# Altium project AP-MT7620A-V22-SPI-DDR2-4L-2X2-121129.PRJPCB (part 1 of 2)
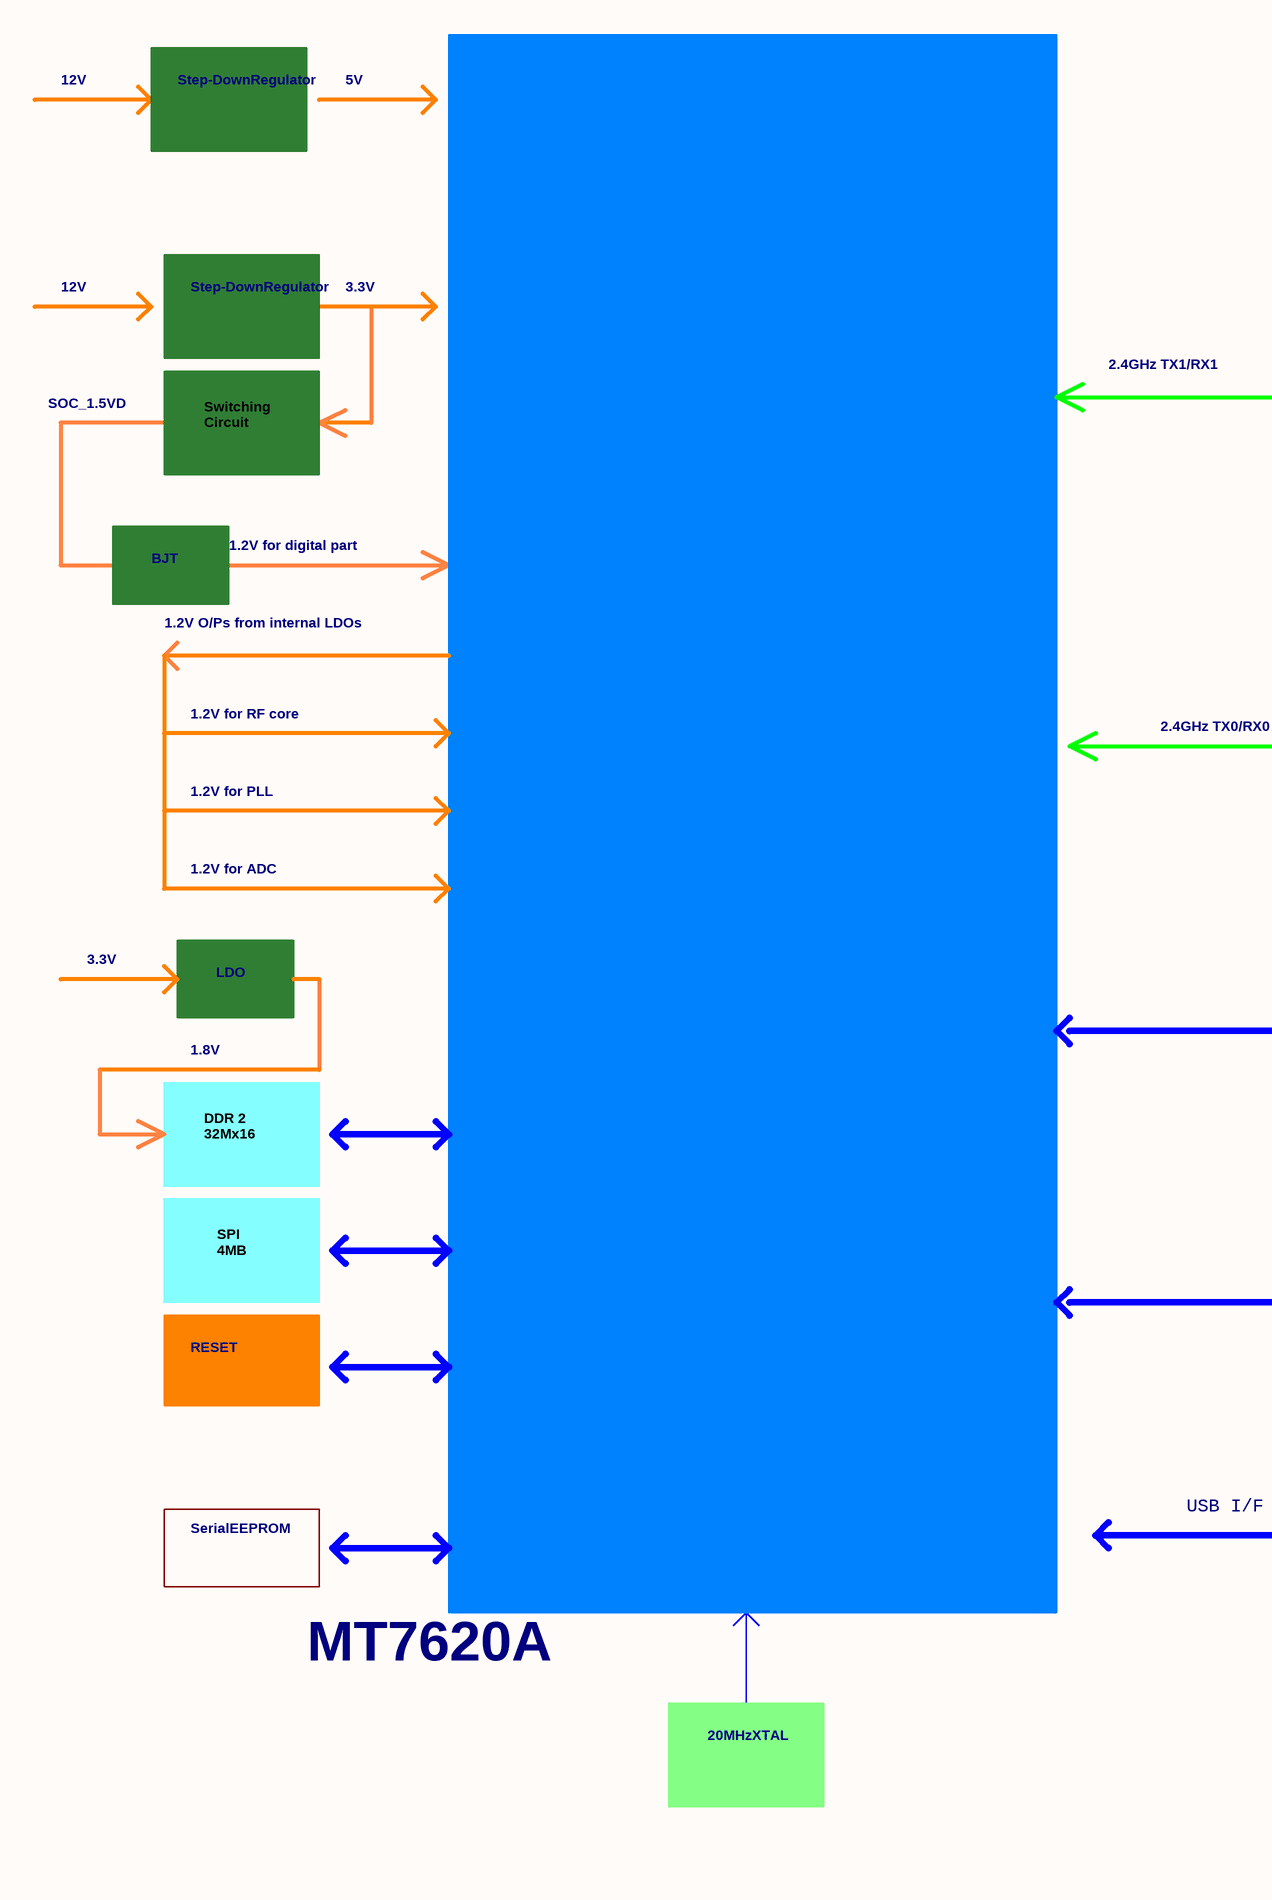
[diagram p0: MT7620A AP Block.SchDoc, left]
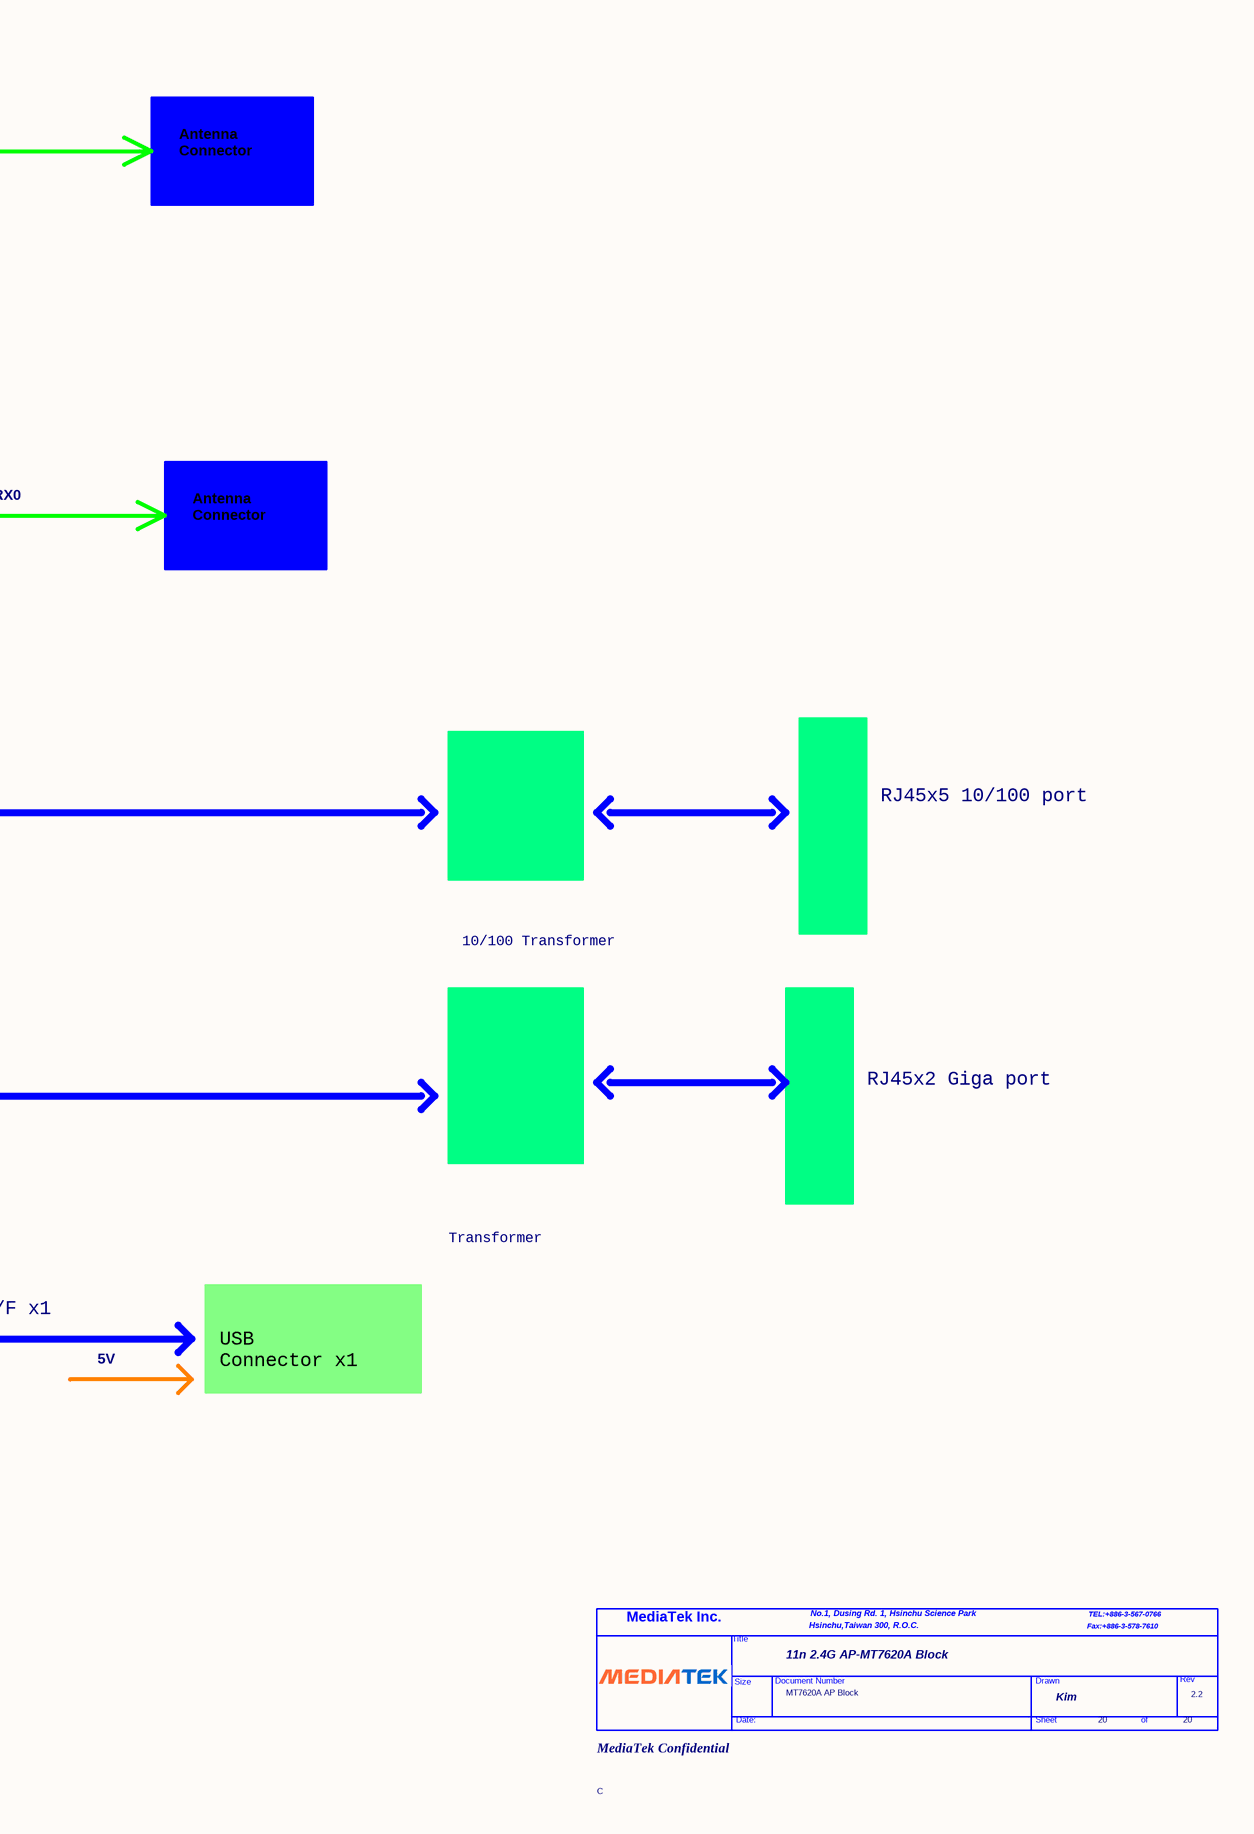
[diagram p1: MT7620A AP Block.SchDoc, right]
20 sheets, 652 parts. Net scope: hierarchical (ports join the sheet entries above them; power ports are global).
Board file: AP-MT7620A-V22-SPI-DDR2-4L-2X2-121129-WS2120.PCBDOC
Sheets:
  MT7620A AP Block.SchDoc
  AP-MT7620A-V22.SchDoc
    2-MEMORY = 23-CONFIG.SchDoc
    2-MEMORY = 22-DDR-CFG.SchDoc
    2-MEMORY = 21-SPI Flash.SchDoc
    3-WLAN = 32-RT5592EP-solt-5G.SchDoc
    3-WLAN = 31-Antenna.SchDoc
    4-ETHERNET = 43-GE2-XMER-RJ45.SchDoc
    4-ETHERNET = 42-GE-XMER-RJ45.SchDoc
    4-ETHERNET = 41-XMER-RJ45.SchDoc
    5-POWER = 5-POWER-RESET.SchDoc
    1-CPU-MT7620A = 18-GPHY2-IP1001.SchDoc
    1-CPU-MT7620A = 17-GPHY1-IP1001.SchDoc
    1-CPU-MT7620A = 16-MT7620A Power-F.SchDoc
    1-CPU-MT7620A = 15-MT7620A Ethernet-E.SchDoc
    1-CPU-MT7620A = 14-MT7620A USB and PCIE.SchDoc
    1-CPU-MT7620A = 13-MT7620A Peripheral-C.SchDoc
    1-CPU-MT7620A = 12-MT7620A DDR I_F-B.SchDoc
    1-CPU-MT7620A = 11-MT7620A RF Front End.SchDoc
    6-LED = 6-LED.SchDoc

## Sheet MT7620A AP Block.SchDoc
size 513 x 386 mm

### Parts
(Parts that share a designator on the sheet are numbered #1, #2 ... from top to bottom, then left to right.)
*#1  PIM: MediaTek Confidential  Page Count: 20  Page Size: C  Title: 11n 2.4G AP-MT7620A Block  RevCode: 2.2  Doc: MT7620A AP Block  Designer: Kim  (hidden comment: TitleBlock_MTK4)  (graphical)

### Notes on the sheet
- 12V
- Step-DownRegulator
- 5V
- 3.3V
- 2.4GHz TX1/RX1
- SOC_1.5VD
- Switching
  Circuit
- Antenna
  Connector
- BJT
- 1.2V for digital part
- 1.2V O/Ps from internal LDOs
- 1.2V for RF core
- 2.4GHz TX0/RX0
- 1.2V for PLL
- 1.2V for ADC
- LDO
- RJ45x5 10/100 port
- 1.8V
- DDR 2
  32Mx16
- 10/100 Transformer
- SPI
  4MB
- RJ45x2 Giga port
- RESET
- Transformer
- SerialEEPROM
- USB I/F x1
- USB
  Connector x1
- MT7620A
- 20MHzXTAL

## Sheet AP-MT7620A-V22.SchDoc
size 386 x 246 mm
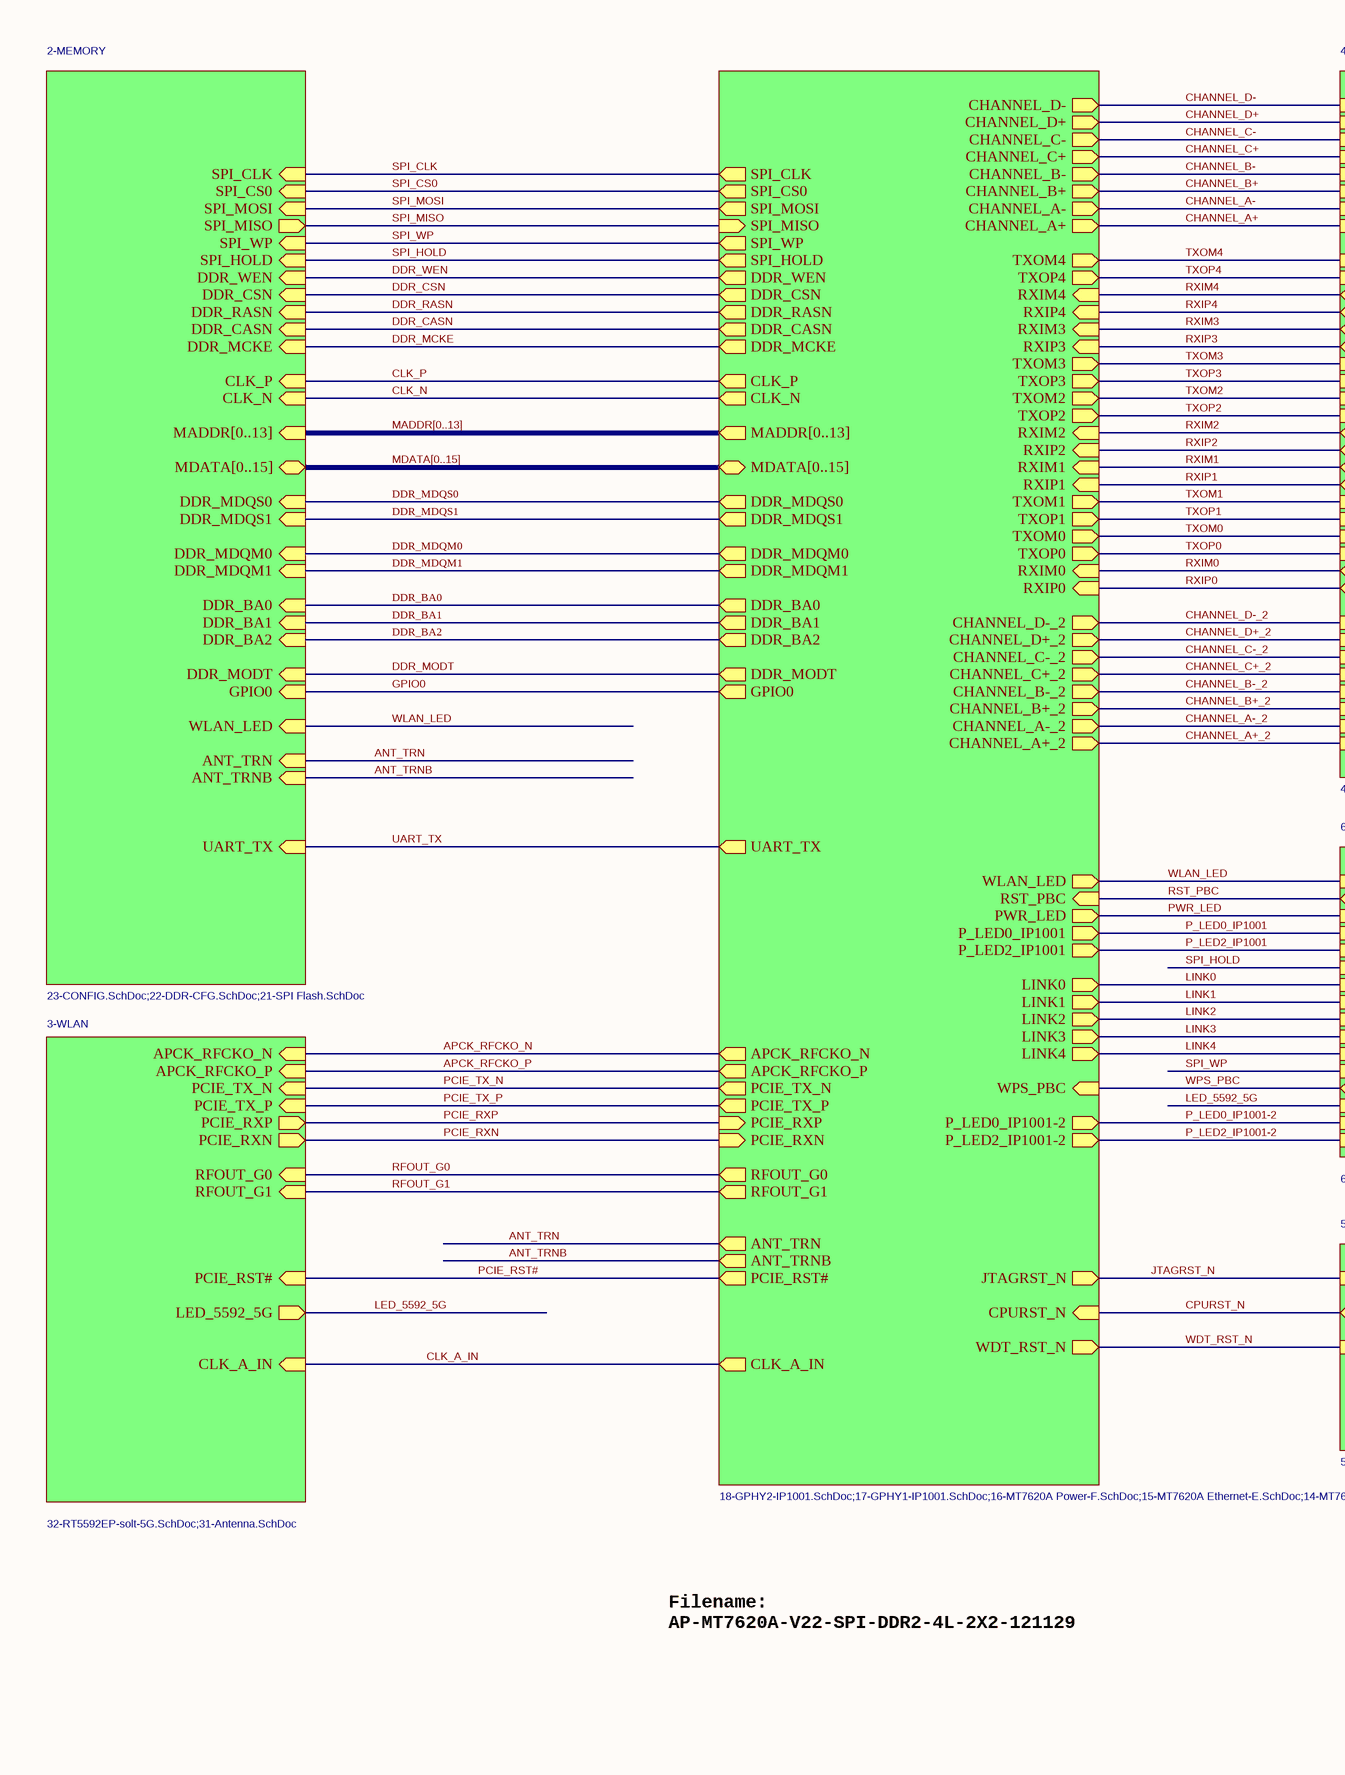
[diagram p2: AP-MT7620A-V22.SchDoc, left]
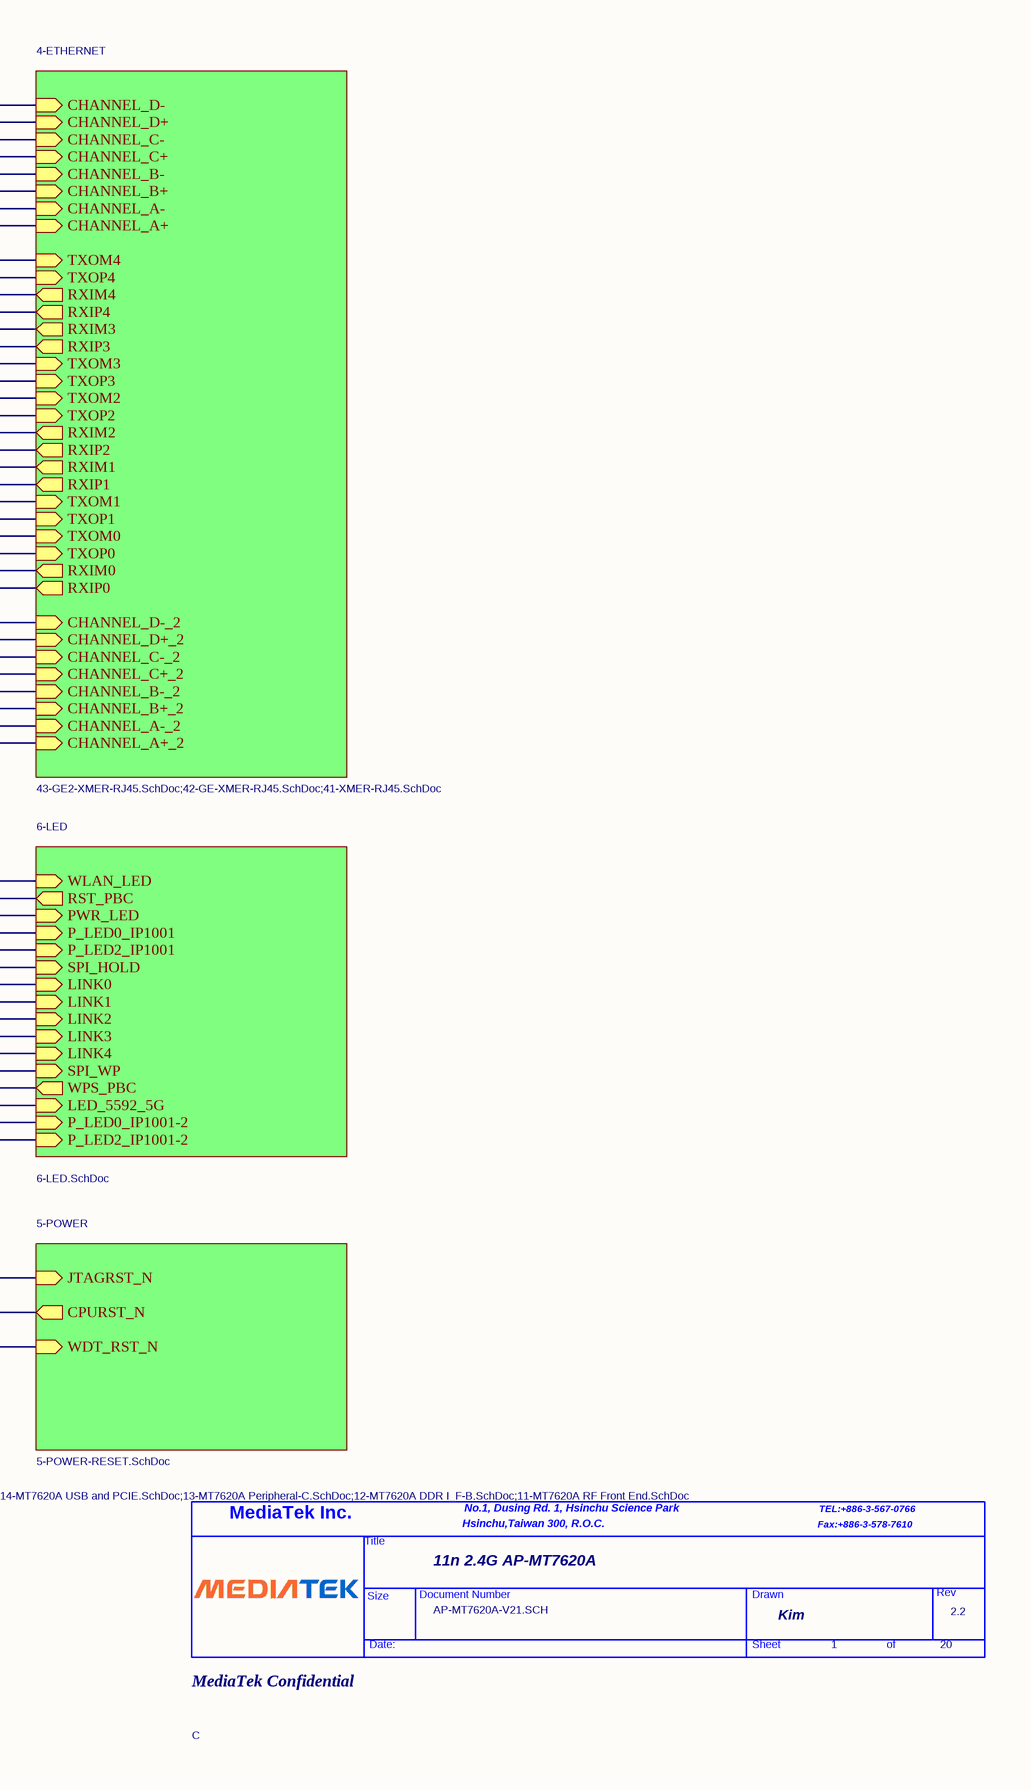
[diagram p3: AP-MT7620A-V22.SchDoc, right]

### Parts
(Parts that share a designator on the sheet are numbered #1, #2 ... from top to bottom, then left to right.)
*#2  PIM: MediaTek Confidential  Page Count: 20  Page Number: 1  Page Size: C  Title: 11n 2.4G AP-MT7620A  RevCode: 2.2  Doc: AP-MT7620A-V21.SCH  Designer: Kim  (hidden comment: TitleBlock_MTK4)  (graphical)

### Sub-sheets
1-CPU-MT7620A = 18-GPHY2-IP1001.SchDoc;17-GPHY1-IP1001.SchDoc;16-MT7620A Power-F.SchDoc;15-MT7620A Ethernet-E.SchDoc;14-MT7620A USB and PCIE.SchDoc;13-MT7620A Peripheral-C.SchDoc;12-MT7620A DDR I_F-B.SchDoc;11-MT7620A RF Front End.SchDoc: SPI_CLK (out), DDR_WEN (out), DDR_CSN (out), CLK_P (out), SPI_CS0 (out), DDR_RASN (out), MADDR[0..13] (out), MDATA[0..15] (bidir), TXOM4 (out), TXOP4 (out), RXIM4 (in), RXIP4 (in), ANT_TRN (out), ANT_TRNB (out), CPURST_N (in), RFOUT_G0 (out), RFOUT_G1 (out), LINK3 (out), LINK2 (out), LINK0 (out), LINK1 (out), LINK4 (out), RXIM3 (in), RXIP0 (in), RXIP1 (in), RXIP2 (in), RXIP3 (in), RXIM0 (in), RXIM1 (in), RXIM2 (in), TXOP0 (out), TXOP1 (out), TXOP2 (out), TXOP3 (out), TXOM0 (out), TXOM1 (out), TXOM2 (out), TXOM3 (out), WPS_PBC (in), DDR_MDQS0 (out), DDR_MDQM0 (out), CLK_N (out), DDR_CASN (out), DDR_BA0 (out), DDR_MCKE (out), SPI_MOSI (out), SPI_MISO (in), UART_TX (out), WLAN_LED (out), SPI_WP (out), SPI_HOLD (out), WDT_RST_N (out), PCIE_RXN (in), PCIE_RXP (in), PCIE_TX_P (out), PCIE_TX_N (out), APCK_RFCKO_P (out), APCK_RFCKO_N (out), CHANNEL_A+ (out), CHANNEL_A- (out), CHANNEL_B+ (out), CHANNEL_B- (out), CHANNEL_C+ (out), CHANNEL_C- (out), CHANNEL_D+ (out), CHANNEL_D- (out), P_LED0_IP1001 (out), P_LED2_IP1001 (out), PCIE_RST# (out), RST_PBC (in), PWR_LED (out), JTAGRST_N (out), DDR_MODT (out), CHANNEL_D-_2 (out), CHANNEL_D+_2 (out), CHANNEL_C-_2 (out), CHANNEL_C+_2 (out), CHANNEL_B-_2 (out), CHANNEL_B+_2 (out), CHANNEL_A-_2 (out), CHANNEL_A+_2 (out), P_LED0_IP1001-2 (out), P_LED2_IP1001-2 (out), GPIO0 (out), CLK_A_IN (out), DDR_MDQS1 (out), DDR_MDQM1 (out), DDR_BA1 (out), DDR_BA2 (out)
2-MEMORY = 23-CONFIG.SchDoc;22-DDR-CFG.SchDoc;21-SPI Flash.SchDoc: SPI_CLK (in), DDR_CSN (in), DDR_WEN (in), CLK_P (in), SPI_CS0 (in), DDR_RASN (in), MADDR[0..13] (in), MDATA[0..15] (bidir), DDR_MDQS0 (in), DDR_MDQM0 (in), CLK_N (in), DDR_CASN (in), DDR_BA0 (in), DDR_MCKE (in), SPI_MOSI (in), SPI_MISO (out), ANT_TRNB (in), ANT_TRN (in), UART_TX (in), GPIO0 (in), SPI_WP (in), SPI_HOLD (in), WLAN_LED (in), DDR_MODT (in), DDR_MDQS1 (in), DDR_MDQM1 (in), DDR_BA1 (in), DDR_BA2 (in)
3-WLAN = 32-RT5592EP-solt-5G.SchDoc;31-Antenna.SchDoc: RFOUT_G0 (in), RFOUT_G1 (in), APCK_RFCKO_N (in), APCK_RFCKO_P (in), PCIE_TX_N (in), PCIE_TX_P (in), PCIE_RXP (out), PCIE_RXN (out), LED_5592_5G (out), PCIE_RST# (in), CLK_A_IN (in)
4-ETHERNET = 43-GE2-XMER-RJ45.SchDoc;42-GE-XMER-RJ45.SchDoc;41-XMER-RJ45.SchDoc: TXOM4 (in), TXOP4 (in), RXIM4 (out), RXIP4 (out), RXIM3 (out), RXIP3 (out), TXOM3 (in), TXOP3 (in), TXOM2 (in), TXOP2 (in), RXIM2 (out), RXIP2 (out), RXIM1 (out), RXIP1 (out), TXOM1 (in), TXOP1 (in), TXOM0 (in), TXOP0 (in), RXIM0 (out), RXIP0 (out), CHANNEL_A+ (in), CHANNEL_A- (in), CHANNEL_B+ (in), CHANNEL_B- (in), CHANNEL_C+ (in), CHANNEL_C- (in), CHANNEL_D+ (in), CHANNEL_D- (in), CHANNEL_D-_2 (in), CHANNEL_D+_2 (in), CHANNEL_C-_2 (in), CHANNEL_C+_2 (in), CHANNEL_B-_2 (in), CHANNEL_B+_2 (in), CHANNEL_A-_2 (in), CHANNEL_A+_2 (in)
5-POWER = 5-POWER-RESET.SchDoc: CPURST_N (out), WDT_RST_N (in), JTAGRST_N (in)
6-LED = 6-LED.SchDoc: LINK0 (in), LINK1 (in), LINK2 (in), LINK3 (in), LINK4 (in), WPS_PBC (out), WLAN_LED (in), P_LED0_IP1001 (in), P_LED2_IP1001 (in), LED_5592_5G (in), RST_PBC (out), PWR_LED (in), SPI_HOLD (in), SPI_WP (in), P_LED2_IP1001-2 (in), P_LED0_IP1001-2 (in)

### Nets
ANT_TRN: sheet 2-MEMORY/ANT_TRN, sheet 1-CPU-MT7620A/ANT_TRN
ANT_TRNB: sheet 2-MEMORY/ANT_TRNB, sheet 1-CPU-MT7620A/ANT_TRNB
APCK_RFCKO_N: sheet 3-WLAN/APCK_RFCKO_N, sheet 1-CPU-MT7620A/APCK_RFCKO_N
APCK_RFCKO_P: sheet 3-WLAN/APCK_RFCKO_P, sheet 1-CPU-MT7620A/APCK_RFCKO_P
CHANNEL_A+: sheet 4-ETHERNET/CHANNEL_A+, sheet 1-CPU-MT7620A/CHANNEL_A+
CHANNEL_A+_2: sheet 4-ETHERNET/CHANNEL_A+_2, sheet 1-CPU-MT7620A/CHANNEL_A+_2
CHANNEL_A-: sheet 4-ETHERNET/CHANNEL_A-, sheet 1-CPU-MT7620A/CHANNEL_A-
CHANNEL_A-_2: sheet 4-ETHERNET/CHANNEL_A-_2, sheet 1-CPU-MT7620A/CHANNEL_A-_2
CHANNEL_B+: sheet 4-ETHERNET/CHANNEL_B+, sheet 1-CPU-MT7620A/CHANNEL_B+
CHANNEL_B+_2: sheet 4-ETHERNET/CHANNEL_B+_2, sheet 1-CPU-MT7620A/CHANNEL_B+_2
CHANNEL_B-: sheet 4-ETHERNET/CHANNEL_B-, sheet 1-CPU-MT7620A/CHANNEL_B-
CHANNEL_B-_2: sheet 4-ETHERNET/CHANNEL_B-_2, sheet 1-CPU-MT7620A/CHANNEL_B-_2
CHANNEL_C+: sheet 4-ETHERNET/CHANNEL_C+, sheet 1-CPU-MT7620A/CHANNEL_C+
CHANNEL_C+_2: sheet 4-ETHERNET/CHANNEL_C+_2, sheet 1-CPU-MT7620A/CHANNEL_C+_2
CHANNEL_C-: sheet 4-ETHERNET/CHANNEL_C-, sheet 1-CPU-MT7620A/CHANNEL_C-
CHANNEL_C-_2: sheet 4-ETHERNET/CHANNEL_C-_2, sheet 1-CPU-MT7620A/CHANNEL_C-_2
CHANNEL_D+: sheet 4-ETHERNET/CHANNEL_D+, sheet 1-CPU-MT7620A/CHANNEL_D+
CHANNEL_D+_2: sheet 4-ETHERNET/CHANNEL_D+_2, sheet 1-CPU-MT7620A/CHANNEL_D+_2
CHANNEL_D-: sheet 4-ETHERNET/CHANNEL_D-, sheet 1-CPU-MT7620A/CHANNEL_D-
CHANNEL_D-_2: sheet 4-ETHERNET/CHANNEL_D-_2, sheet 1-CPU-MT7620A/CHANNEL_D-_2
CLK_A_IN: sheet 3-WLAN/CLK_A_IN, sheet 1-CPU-MT7620A/CLK_A_IN
CLK_N: sheet 2-MEMORY/CLK_N, sheet 1-CPU-MT7620A/CLK_N
CLK_P: sheet 2-MEMORY/CLK_P, sheet 1-CPU-MT7620A/CLK_P
CPURST_N: sheet 5-POWER/CPURST_N, sheet 1-CPU-MT7620A/CPURST_N
DDR_BA0: sheet 2-MEMORY/DDR_BA0, sheet 1-CPU-MT7620A/DDR_BA0
DDR_BA1: sheet 2-MEMORY/DDR_BA1, sheet 1-CPU-MT7620A/DDR_BA1
DDR_BA2: sheet 2-MEMORY/DDR_BA2, sheet 1-CPU-MT7620A/DDR_BA2
DDR_CASN: sheet 2-MEMORY/DDR_CASN, sheet 1-CPU-MT7620A/DDR_CASN
DDR_CSN: sheet 2-MEMORY/DDR_CSN, sheet 1-CPU-MT7620A/DDR_CSN
DDR_MCKE: sheet 2-MEMORY/DDR_MCKE, sheet 1-CPU-MT7620A/DDR_MCKE
DDR_MDQM0: sheet 2-MEMORY/DDR_MDQM0, sheet 1-CPU-MT7620A/DDR_MDQM0
DDR_MDQM1: sheet 2-MEMORY/DDR_MDQM1, sheet 1-CPU-MT7620A/DDR_MDQM1
DDR_MDQS0: sheet 2-MEMORY/DDR_MDQS0, sheet 1-CPU-MT7620A/DDR_MDQS0
DDR_MDQS1: sheet 2-MEMORY/DDR_MDQS1, sheet 1-CPU-MT7620A/DDR_MDQS1
DDR_MODT: sheet 2-MEMORY/DDR_MODT, sheet 1-CPU-MT7620A/DDR_MODT
DDR_RASN: sheet 2-MEMORY/DDR_RASN, sheet 1-CPU-MT7620A/DDR_RASN
DDR_WEN: sheet 2-MEMORY/DDR_WEN, sheet 1-CPU-MT7620A/DDR_WEN
GPIO0: sheet 2-MEMORY/GPIO0, sheet 1-CPU-MT7620A/GPIO0
JTAGRST_N: sheet 5-POWER/JTAGRST_N, sheet 1-CPU-MT7620A/JTAGRST_N
LED_5592_5G: sheet 3-WLAN/LED_5592_5G, sheet 6-LED/LED_5592_5G
LINK0: sheet 1-CPU-MT7620A/LINK0, sheet 6-LED/LINK0
LINK1: sheet 1-CPU-MT7620A/LINK1, sheet 6-LED/LINK1
LINK2: sheet 1-CPU-MT7620A/LINK2, sheet 6-LED/LINK2
LINK3: sheet 1-CPU-MT7620A/LINK3, sheet 6-LED/LINK3
LINK4: sheet 1-CPU-MT7620A/LINK4, sheet 6-LED/LINK4
P_LED0_IP1001: sheet 1-CPU-MT7620A/P_LED0_IP1001, sheet 6-LED/P_LED0_IP1001
P_LED0_IP1001-2: sheet 1-CPU-MT7620A/P_LED0_IP1001-2, sheet 6-LED/P_LED0_IP1001-2
P_LED2_IP1001: sheet 1-CPU-MT7620A/P_LED2_IP1001, sheet 6-LED/P_LED2_IP1001
P_LED2_IP1001-2: sheet 1-CPU-MT7620A/P_LED2_IP1001-2, sheet 6-LED/P_LED2_IP1001-2
PCIE_RST#: sheet 3-WLAN/PCIE_RST#, sheet 1-CPU-MT7620A/PCIE_RST#
PCIE_RXN: sheet 3-WLAN/PCIE_RXN, sheet 1-CPU-MT7620A/PCIE_RXN
PCIE_RXP: sheet 3-WLAN/PCIE_RXP, sheet 1-CPU-MT7620A/PCIE_RXP
PCIE_TX_N: sheet 3-WLAN/PCIE_TX_N, sheet 1-CPU-MT7620A/PCIE_TX_N
PCIE_TX_P: sheet 3-WLAN/PCIE_TX_P, sheet 1-CPU-MT7620A/PCIE_TX_P
PWR_LED: sheet 1-CPU-MT7620A/PWR_LED, sheet 6-LED/PWR_LED
RFOUT_G0: sheet 3-WLAN/RFOUT_G0, sheet 1-CPU-MT7620A/RFOUT_G0
RFOUT_G1: sheet 3-WLAN/RFOUT_G1, sheet 1-CPU-MT7620A/RFOUT_G1
RST_PBC: sheet 1-CPU-MT7620A/RST_PBC, sheet 6-LED/RST_PBC
RXIM0: sheet 4-ETHERNET/RXIM0, sheet 1-CPU-MT7620A/RXIM0
RXIM1: sheet 4-ETHERNET/RXIM1, sheet 1-CPU-MT7620A/RXIM1
RXIM2: sheet 4-ETHERNET/RXIM2, sheet 1-CPU-MT7620A/RXIM2
RXIM3: sheet 4-ETHERNET/RXIM3, sheet 1-CPU-MT7620A/RXIM3
RXIM4: sheet 4-ETHERNET/RXIM4, sheet 1-CPU-MT7620A/RXIM4
RXIP0: sheet 4-ETHERNET/RXIP0, sheet 1-CPU-MT7620A/RXIP0
RXIP1: sheet 4-ETHERNET/RXIP1, sheet 1-CPU-MT7620A/RXIP1
RXIP2: sheet 4-ETHERNET/RXIP2, sheet 1-CPU-MT7620A/RXIP2
RXIP3: sheet 4-ETHERNET/RXIP3, sheet 1-CPU-MT7620A/RXIP3
RXIP4: sheet 4-ETHERNET/RXIP4, sheet 1-CPU-MT7620A/RXIP4
SPI_CLK: sheet 2-MEMORY/SPI_CLK, sheet 1-CPU-MT7620A/SPI_CLK
SPI_CS0: sheet 2-MEMORY/SPI_CS0, sheet 1-CPU-MT7620A/SPI_CS0
SPI_HOLD: sheet 2-MEMORY/SPI_HOLD, sheet 1-CPU-MT7620A/SPI_HOLD, sheet 6-LED/SPI_HOLD
SPI_MISO: sheet 2-MEMORY/SPI_MISO, sheet 1-CPU-MT7620A/SPI_MISO
SPI_MOSI: sheet 2-MEMORY/SPI_MOSI, sheet 1-CPU-MT7620A/SPI_MOSI
SPI_WP: sheet 2-MEMORY/SPI_WP, sheet 1-CPU-MT7620A/SPI_WP, sheet 6-LED/SPI_WP
TXOM0: sheet 4-ETHERNET/TXOM0, sheet 1-CPU-MT7620A/TXOM0
TXOM1: sheet 4-ETHERNET/TXOM1, sheet 1-CPU-MT7620A/TXOM1
TXOM2: sheet 4-ETHERNET/TXOM2, sheet 1-CPU-MT7620A/TXOM2
TXOM3: sheet 4-ETHERNET/TXOM3, sheet 1-CPU-MT7620A/TXOM3
TXOM4: sheet 4-ETHERNET/TXOM4, sheet 1-CPU-MT7620A/TXOM4
TXOP0: sheet 4-ETHERNET/TXOP0, sheet 1-CPU-MT7620A/TXOP0
TXOP1: sheet 4-ETHERNET/TXOP1, sheet 1-CPU-MT7620A/TXOP1
TXOP2: sheet 4-ETHERNET/TXOP2, sheet 1-CPU-MT7620A/TXOP2
TXOP3: sheet 4-ETHERNET/TXOP3, sheet 1-CPU-MT7620A/TXOP3
TXOP4: sheet 4-ETHERNET/TXOP4, sheet 1-CPU-MT7620A/TXOP4
UART_TX: sheet 2-MEMORY/UART_TX, sheet 1-CPU-MT7620A/UART_TX
WDT_RST_N: sheet 5-POWER/WDT_RST_N, sheet 1-CPU-MT7620A/WDT_RST_N
WLAN_LED: sheet 2-MEMORY/WLAN_LED, sheet 1-CPU-MT7620A/WLAN_LED, sheet 6-LED/WLAN_LED
WPS_PBC: sheet 1-CPU-MT7620A/WPS_PBC, sheet 6-LED/WPS_PBC

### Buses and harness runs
bus MADDR[0..13] = sheet 1-CPU-MT7620A/MADDR[0..13] = sheet 2-MEMORY/MADDR[0..13]
bus MDATA[0..15] = sheet 1-CPU-MT7620A/MDATA[0..15] = sheet 2-MEMORY/MDATA[0..15]

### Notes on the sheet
- Filename:
  AP-MT7620A-V22-SPI-DDR2-4L-2X2-121129

## Sheet 23-CONFIG.SchDoc
size 386 x 246 mm
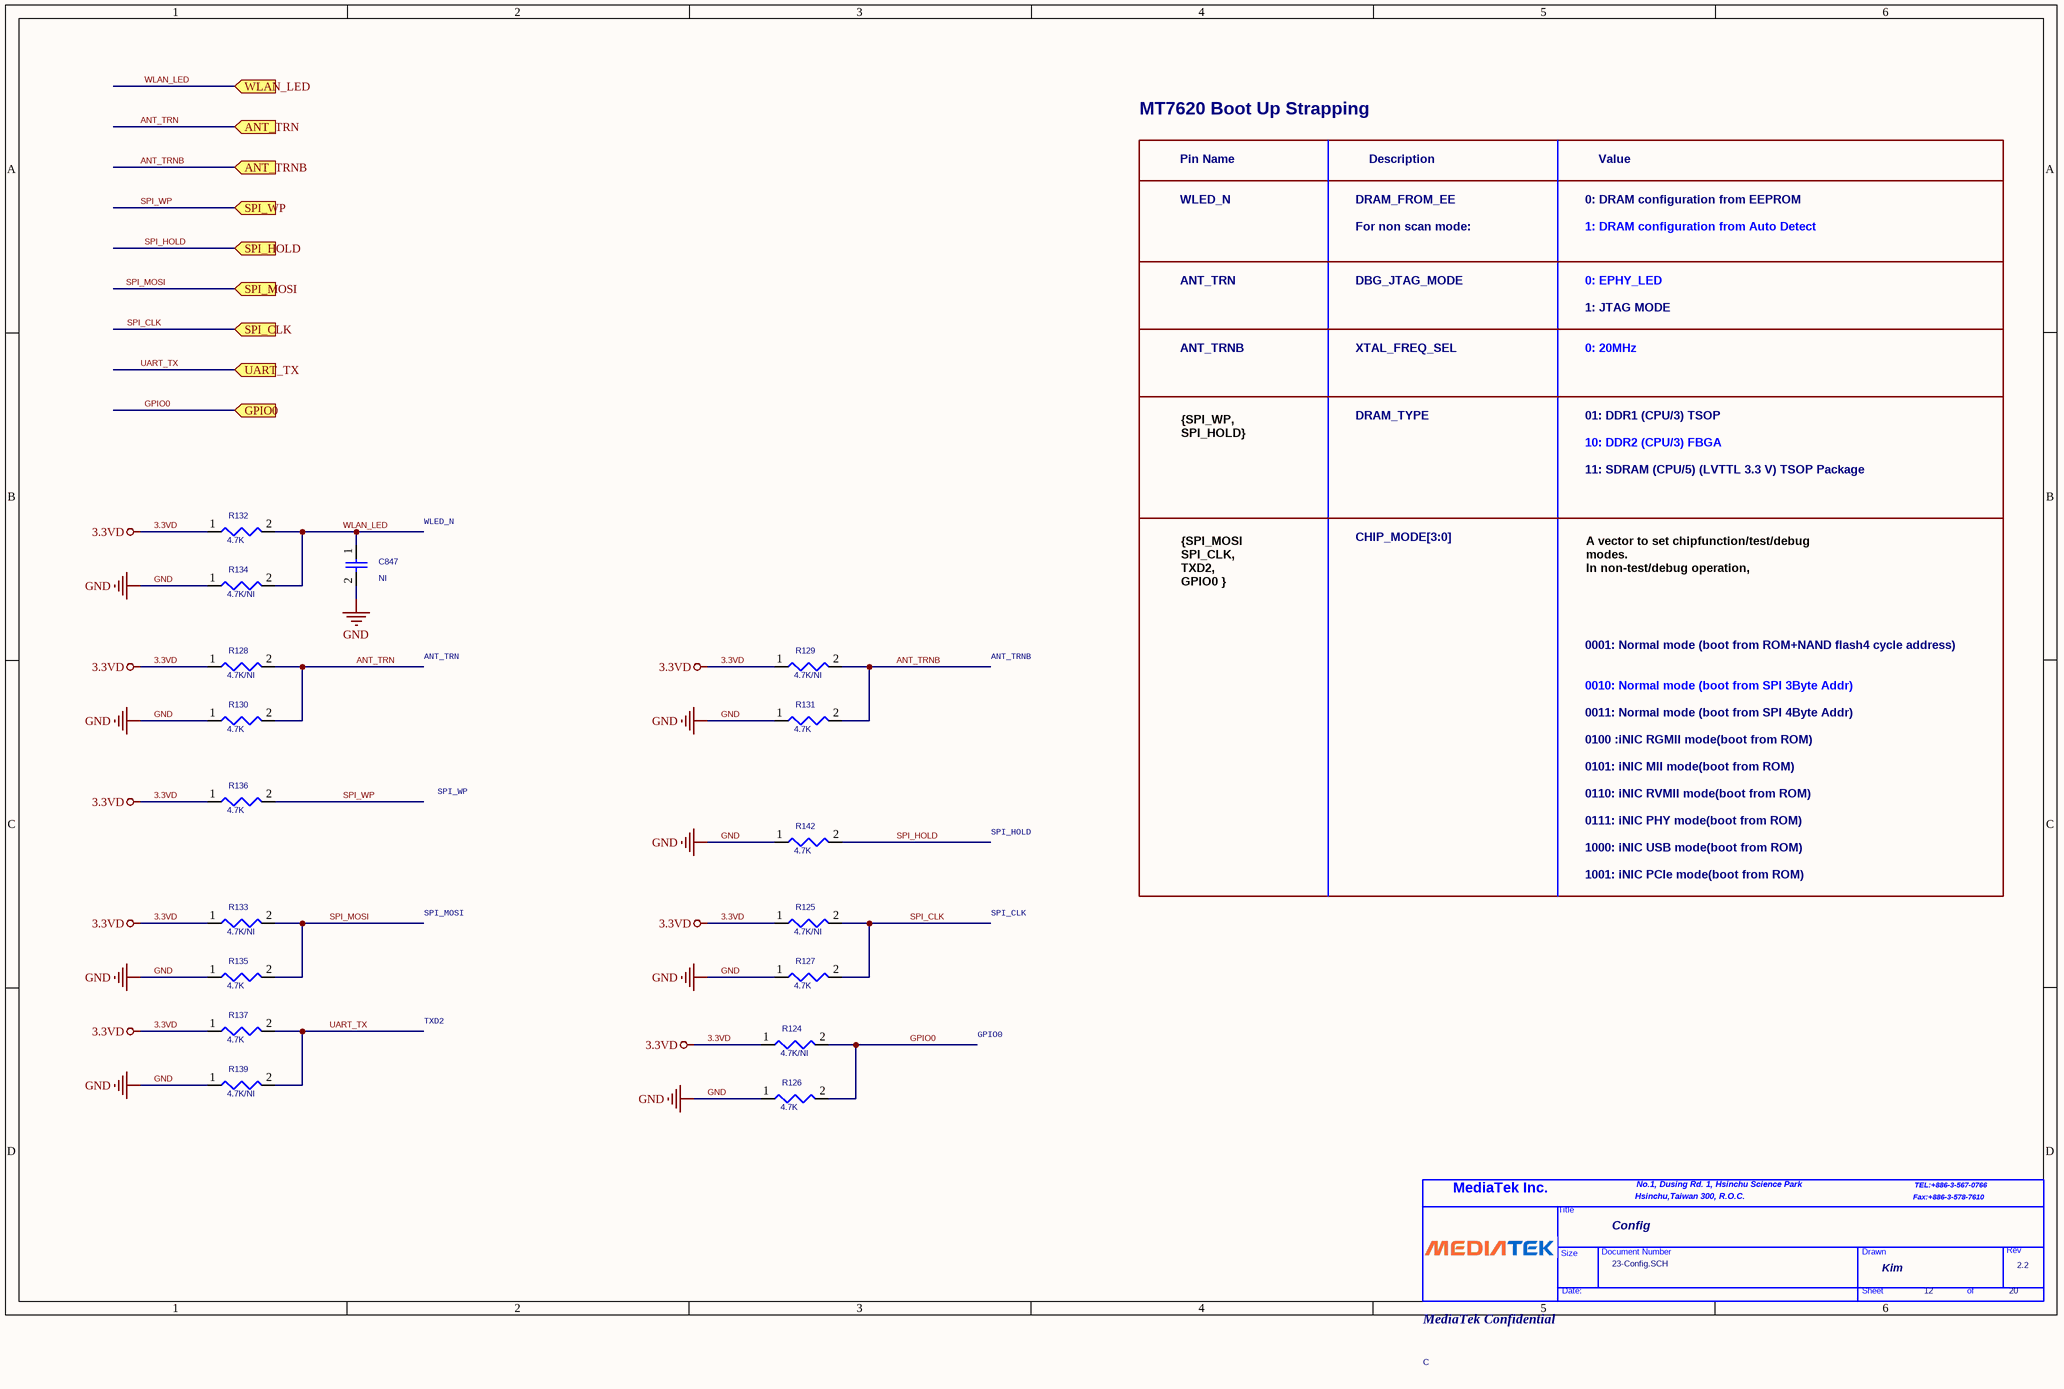
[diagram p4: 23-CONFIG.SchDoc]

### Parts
(Parts that share a designator on the sheet are numbered #1, #2 ... from top to bottom, then left to right.)
*#3  PIM: MediaTek Confidential  Page Count: 20  Page Number: 12  Page Size: C  Title: Config  RevCode: 2.2  Doc: 23-Config.SCH  Designer: Kim  (hidden comment: TitleBlock_MTK4)  (graphical)
C847  NI  [C0402]
R124  4.7K/NI  [R0402]
R125  4.7K/NI  [R0402]
R126  4.7K  [R0402]
R127  4.7K  [R0402]
R128  4.7K/NI  [R0402]
R129  4.7K/NI  [R0402]
R130  4.7K  [R0402]
R131  4.7K  [R0402]
R132  4.7K  [R0402]
R133  4.7K/NI  [R0402]
R134  4.7K/NI  [R0402]
R135  4.7K  [R0402]
R136  4.7K  [R0402]
R137  4.7K  [R0402]
R139  4.7K/NI  [R0402]
R142  4.7K  [R0402]

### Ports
ANT_TRN (in), ANT_TRNB (in), GPIO0 (in), SPI_CLK (in), SPI_HOLD (in), SPI_MOSI (in), SPI_WP (in), UART_TX (in), WLAN_LED (in)

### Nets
3.3VD: R124.1 R125.1 R128.1 R129.1 R132.1 R133.1 R136.1 R137.1
GND: C847.2 R126.1 R127.1 R130.1 R131.1 R134.1 R135.1 R139.1 R142.1
ANT_TRN: R128.2 R130.2 ; port ANT_TRN
ANT_TRNB: R129.2 R131.2 ; port ANT_TRNB
GPIO0: R124.2 R126.2 ; port GPIO0
SPI_CLK: R125.2 R127.2 ; port SPI_CLK
SPI_HOLD: R142.2 ; port SPI_HOLD
SPI_MOSI: R133.2 R135.2 ; port SPI_MOSI
SPI_WP: R136.2 ; port SPI_WP
UART_TX: R137.2 R139.2 ; port UART_TX
WLAN_LED: C847.1 R132.2 R134.2 ; port WLAN_LED

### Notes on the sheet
- MT7620 Boot Up Strapping
- Pin Name
- Description
- Value
- WLED_N
- DRAM_FROM_EE
- For non scan mode:
- 0: DRAM configuration from EEPROM
- 1: DRAM configuration from Auto Detect
- ANT_TRN
- DBG_JTAG_MODE
- 0: EPHY_LED
- 1: JTAG MODE
- ANT_TRNB
- XTAL_FREQ_SEL
- 0: 20MHz
- {SPI_WP,
  SPI_HOLD}
- DRAM_TYPE
- 01: DDR1 (CPU/3) TSOP
- 10: DDR2 (CPU/3) FBGA
- 11: SDRAM (CPU/5) (LVTTL 3.3 V) TSOP Package
- CHIP_MODE[3:0]
- A vector to set chipfunction/test/debug modes.
  In non-test/debug operation,
- {SPI_MOSI
  SPI_CLK,
  TXD2,
  GPIO0 }
- 0001: Normal mode (boot from ROM+NAND flash4 cycle address)
- 0010: Normal mode (boot from SPI 3Byte Addr)
- 0011: Normal mode (boot from SPI 4Byte Addr)
- SPI_WP
- 0100 :iNIC RGMII mode(boot from ROM)
- 0101: iNIC MII mode(boot from ROM)
- 0110: iNIC RVMII mode(boot from ROM)
- SPI_HOLD
- 1000: iNIC USB mode(boot from ROM)
- 0111: iNIC PHY mode(boot from ROM)
- SPI_MOSI
- SPI_CLK
- 1001: iNIC PCIe mode(boot from ROM)
- TXD2
- GPIO0

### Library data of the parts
C847 = CAP/0402
R124-R137 R139 R142 = RES/0402_Dup1

## Sheet 22-DDR-CFG.SchDoc
size 386 x 304 mm
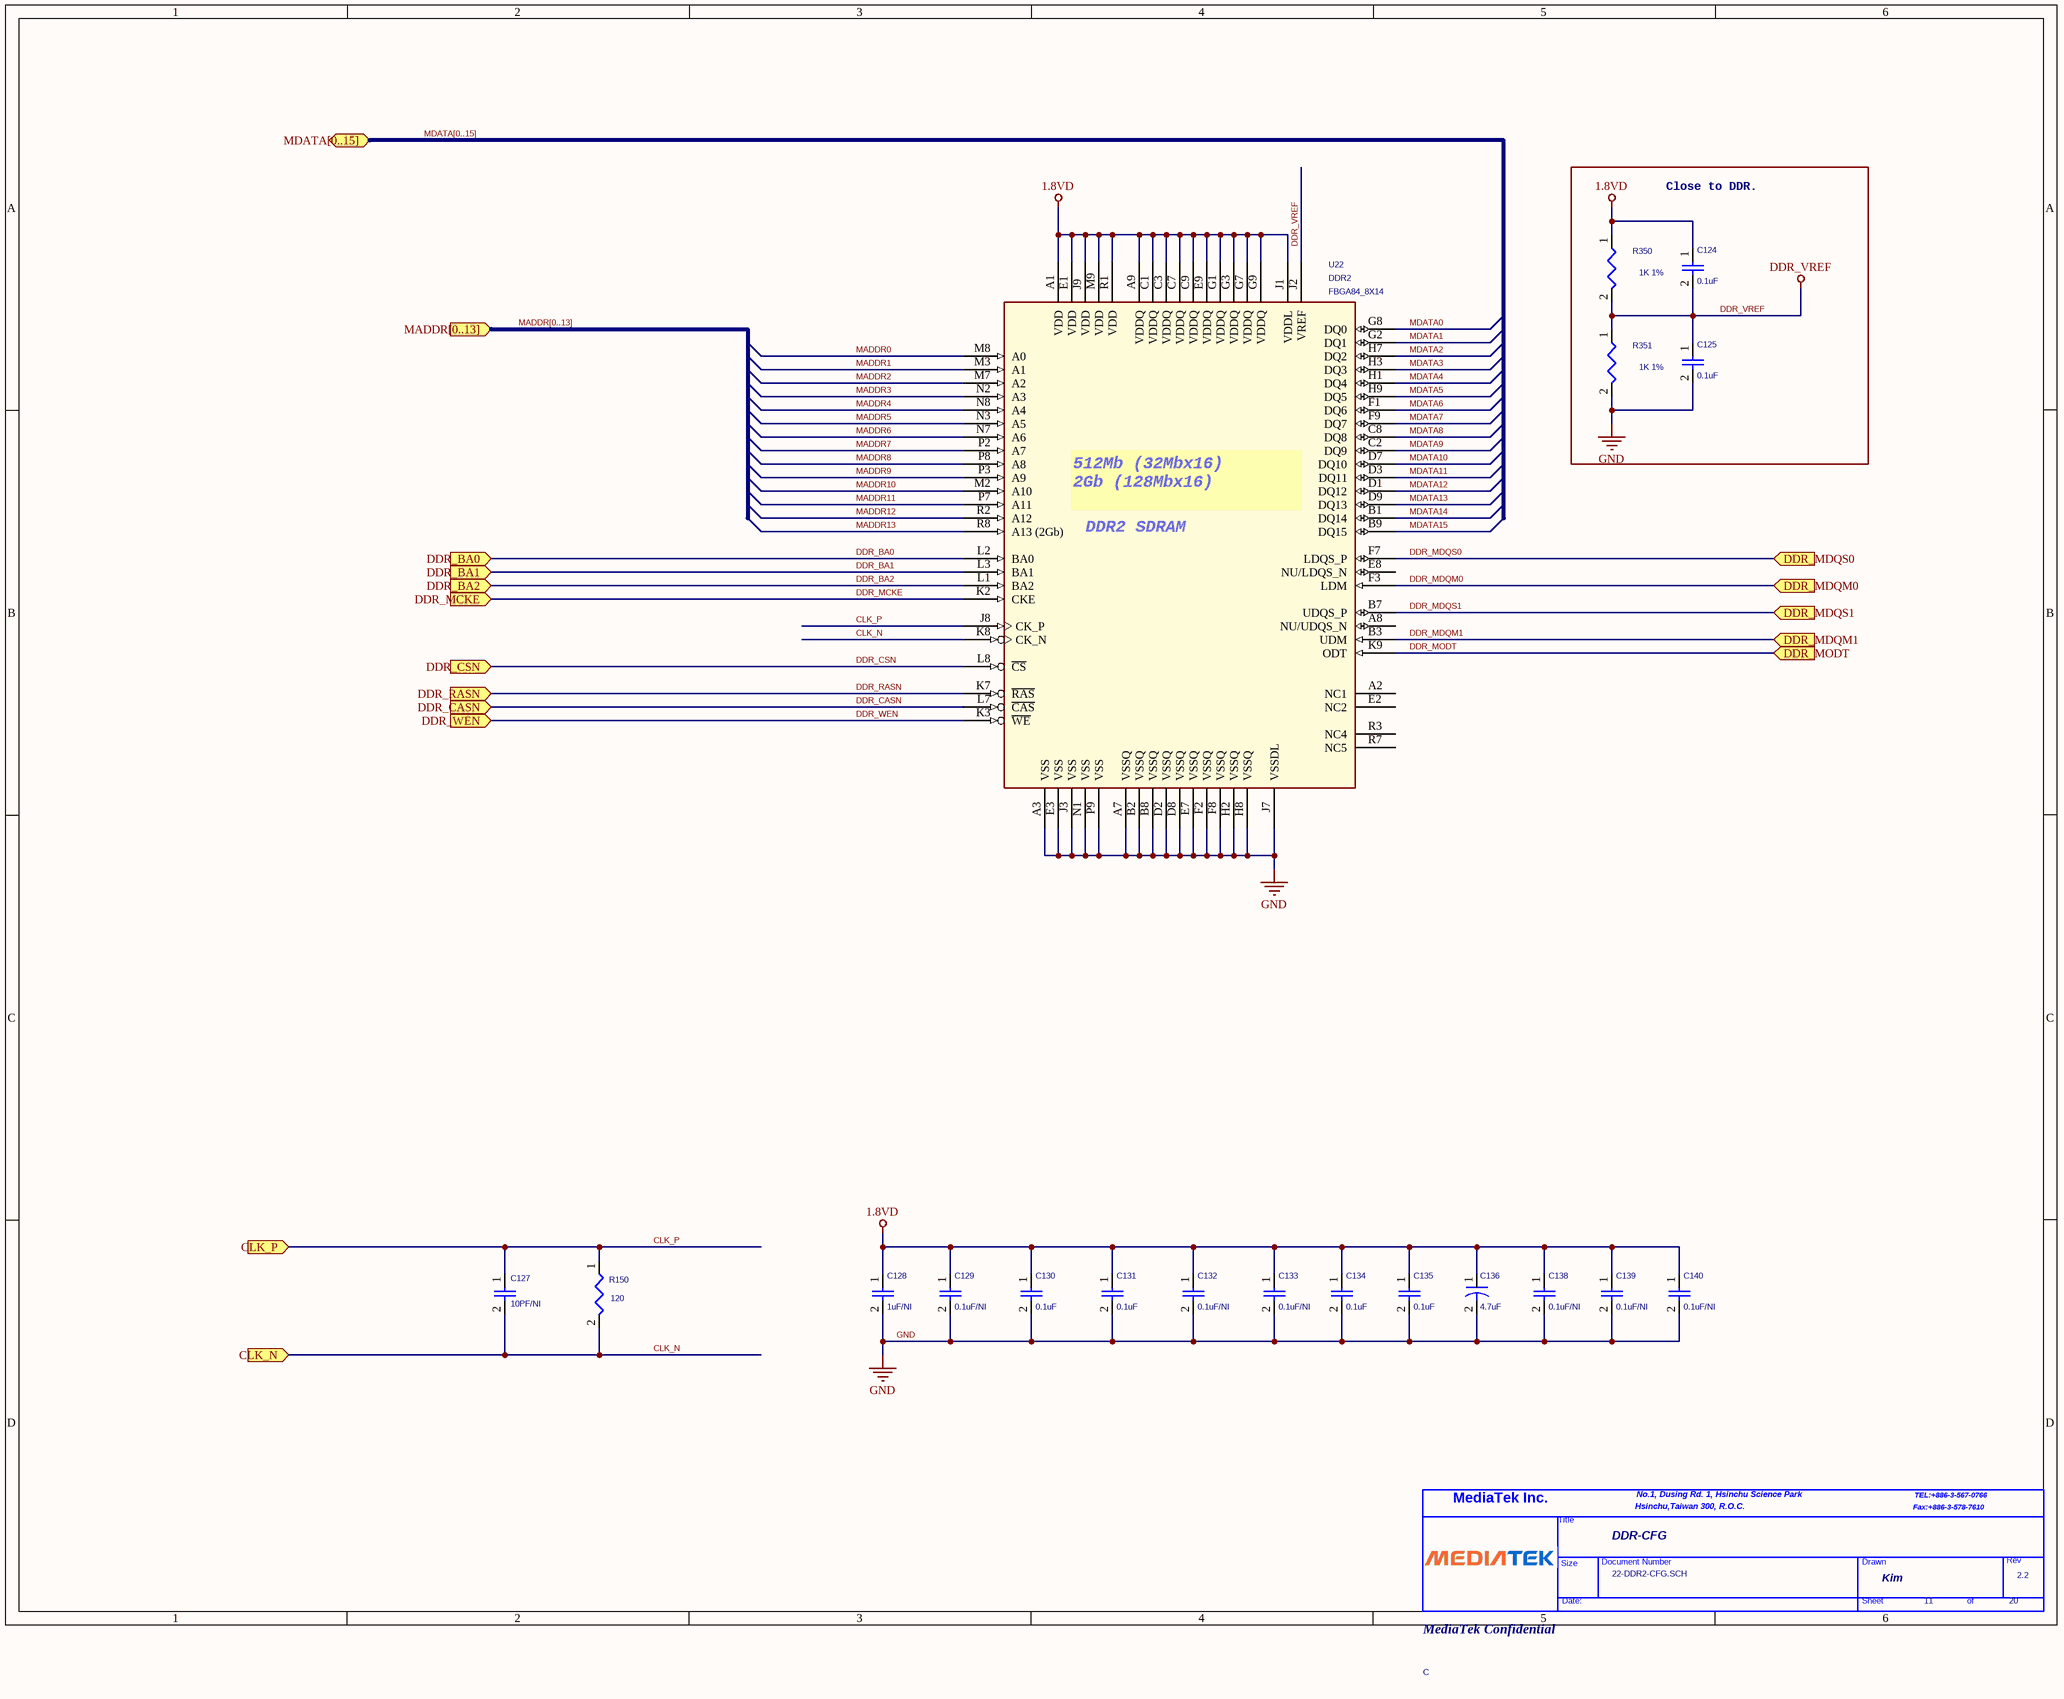
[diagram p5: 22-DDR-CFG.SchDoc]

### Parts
(Parts that share a designator on the sheet are numbered #1, #2 ... from top to bottom, then left to right.)
*#4  PIM: MediaTek Confidential  Page Count: 20  Page Number: 11  Page Size: C  Title: DDR-CFG  RevCode: 2.2  Doc: 22-DDR2-CFG.SCH  Designer: Kim  (hidden comment: TitleBlock_MTK4)  (graphical)
C124  0.1uF  [C0402]
C125  0.1uF  [C0402]
C127  10PF/NI  [C0402]
C128  1uF/NI  [C0402]
C129  0.1uF/NI  [C0402]
C130  0.1uF  [C0402]
C131  0.1uF  [C0402]
C132  0.1uF/NI  [C0402]
C133  0.1uF/NI  [C0402]
C134  0.1uF  [C0402]
C135  0.1uF  [C0402]
C136  4.7uF  [C0805]
C138  0.1uF/NI  [C0402]
C139  0.1uF/NI  [C0402]
C140  0.1uF/NI  [C0402]
R150  120  [R0402]
R350  1K 1%  [R0402]
R351  1K 1%  [R0402]
U22  DDR2  Package: FBGA84_8X14  [WBGA84/SMD/P0.8/W9751G6IB]

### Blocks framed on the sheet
Close to DDR.: C124 C125 R350 R351

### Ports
CLK_N (in), CLK_P (in), DDR_BA0 (in), DDR_BA1 (in), DDR_BA2 (in), DDR_CASN (in), DDR_CSN (in), DDR_MCKE (in), DDR_MDQM0 (in), DDR_MDQM1 (in), DDR_MDQS0 (in), DDR_MDQS1 (in), DDR_MODT (in), DDR_RASN (in), DDR_WEN (in), MADDR[0..13] (in), MDATA[0..15] (bidir)

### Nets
1.8VD: C124.1 C128.1 C129.1 C130.1 C131.1 C132.1 C133.1 C134.1 C135.1 C136.1 C138.1 C139.1 C140.1 R350.1 U22.A1(VDD) U22.A9(VDDQ) U22.C1(VDDQ) U22.C3(VDDQ) U22.C7(VDDQ) U22.C9(VDDQ) U22.E1(VDD) U22.E9(VDDQ) U22.G1(VDDQ) U22.G3(VDDQ) U22.G7(VDDQ) U22.G9(VDDQ) U22.J1(VDDL) U22.J9(VDD) U22.M9(VDD) U22.R1(VDD)
DDR_VREF: C124.2 C125.1 R350.2 R351.1 U22.J2(VREF)
GND: C125.2 C128.2 C129.2 C130.2 C131.2 C132.2 C133.2 C134.2 C135.2 C136.2 C138.2 C139.2 C140.2 R351.2 U22.A3(VSS) U22.A7(VSSQ) U22.B2(VSSQ) U22.B8(VSSQ) U22.D2(VSSQ) U22.D8(VSSQ) U22.E3(VSS) U22.E7(VSSQ) U22.F2(VSSQ) U22.F8(VSSQ) U22.H2(VSSQ) U22.H8(VSSQ) U22.J3(VSS) U22.J7(VSSDL) U22.N1(VSS) U22.P9(VSS)
CLK_N: C127.2 R150.2 U22.K8(CK_N) ; port CLK_N
CLK_P: C127.1 R150.1 U22.J8(CK_P) ; port CLK_P
DDR_BA0: U22.L2(BA0) ; port DDR_BA0
DDR_BA1: U22.L3(BA1) ; port DDR_BA1
DDR_BA2: U22.L1(BA2) ; port DDR_BA2
DDR_CASN: U22.L7(~{CAS}) ; port DDR_CASN
DDR_CSN: U22.L8(~{CS}) ; port DDR_CSN
DDR_MCKE: U22.K2(CKE) ; port DDR_MCKE
DDR_MDQM0: U22.F3(LDM) ; port DDR_MDQM0
DDR_MDQM1: U22.B3(UDM) ; port DDR_MDQM1
DDR_MDQS0: U22.F7(LDQS_P) ; port DDR_MDQS0
DDR_MDQS1: U22.B7(UDQS_P) ; port DDR_MDQS1
DDR_MODT: U22.K9(ODT) ; port DDR_MODT
DDR_RASN: U22.K7(~{RAS}) ; port DDR_RASN
DDR_WEN: U22.K3(~{WE}) ; port DDR_WEN
MADDR0: U22.M8(A0)
MADDR1: U22.M3(A1)
MADDR2: U22.M7(A2)
MADDR3: U22.N2(A3)
MADDR4: U22.N8(A4)
MADDR5: U22.N3(A5)
MADDR6: U22.N7(A6)
MADDR7: U22.P2(A7)
MADDR8: U22.P8(A8)
MADDR9: U22.P3(A9)
MADDR10: U22.M2(A10)
MADDR11: U22.P7(A11)
MADDR12: U22.R2(A12)
MADDR13: U22.R8(A13_(2Gb))
MDATA0: U22.G8(DQ0)
MDATA1: U22.G2(DQ1)
MDATA2: U22.H7(DQ2)
MDATA3: U22.H3(DQ3)
MDATA4: U22.H1(DQ4)
MDATA5: U22.H9(DQ5)
MDATA6: U22.F1(DQ6)
MDATA7: U22.F9(DQ7)
MDATA8: U22.C8(DQ8)
MDATA9: U22.C2(DQ9)
MDATA10: U22.D7(DQ10)
MDATA11: U22.D3(DQ11)
MDATA12: U22.D1(DQ12)
MDATA13: U22.D9(DQ13)
MDATA14: U22.B1(DQ14)
MDATA15: U22.B9(DQ15)

Not connected (* = marked no-connect by the designer): U22 A2(NC1) A8(NU/UDQS_N) E2(NC2) E8(NU/LDQS_N) R3(NC4) R7(NC5)

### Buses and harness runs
bus MADDR[0..13] = port MADDR[0..13]
bus MDATA[0..15] = port MDATA[0..15]

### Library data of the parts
C124 C125 C127 C129-C135 C138-C140 = CAP/0402_Dup1
C128 = CAP/0402_Dup2
C136 = CAP/0805_Dup1
R150 R350 R351 = RES/0402_Dup1
U22 = MT47H16M16BG_1: IC-SDRAM-MT47H-FBGA84; NC: A2,E2,L1,R3,R7,R8; Vendor PN: MT47H16M16BG-5E; Vendor: MICRON; Description 2: 5nS 32MX16 DDR2; P_Number: xx; P_Description: W9725G6IB

## Sheet 21-SPI Flash.SchDoc
size 246 x 182 mm
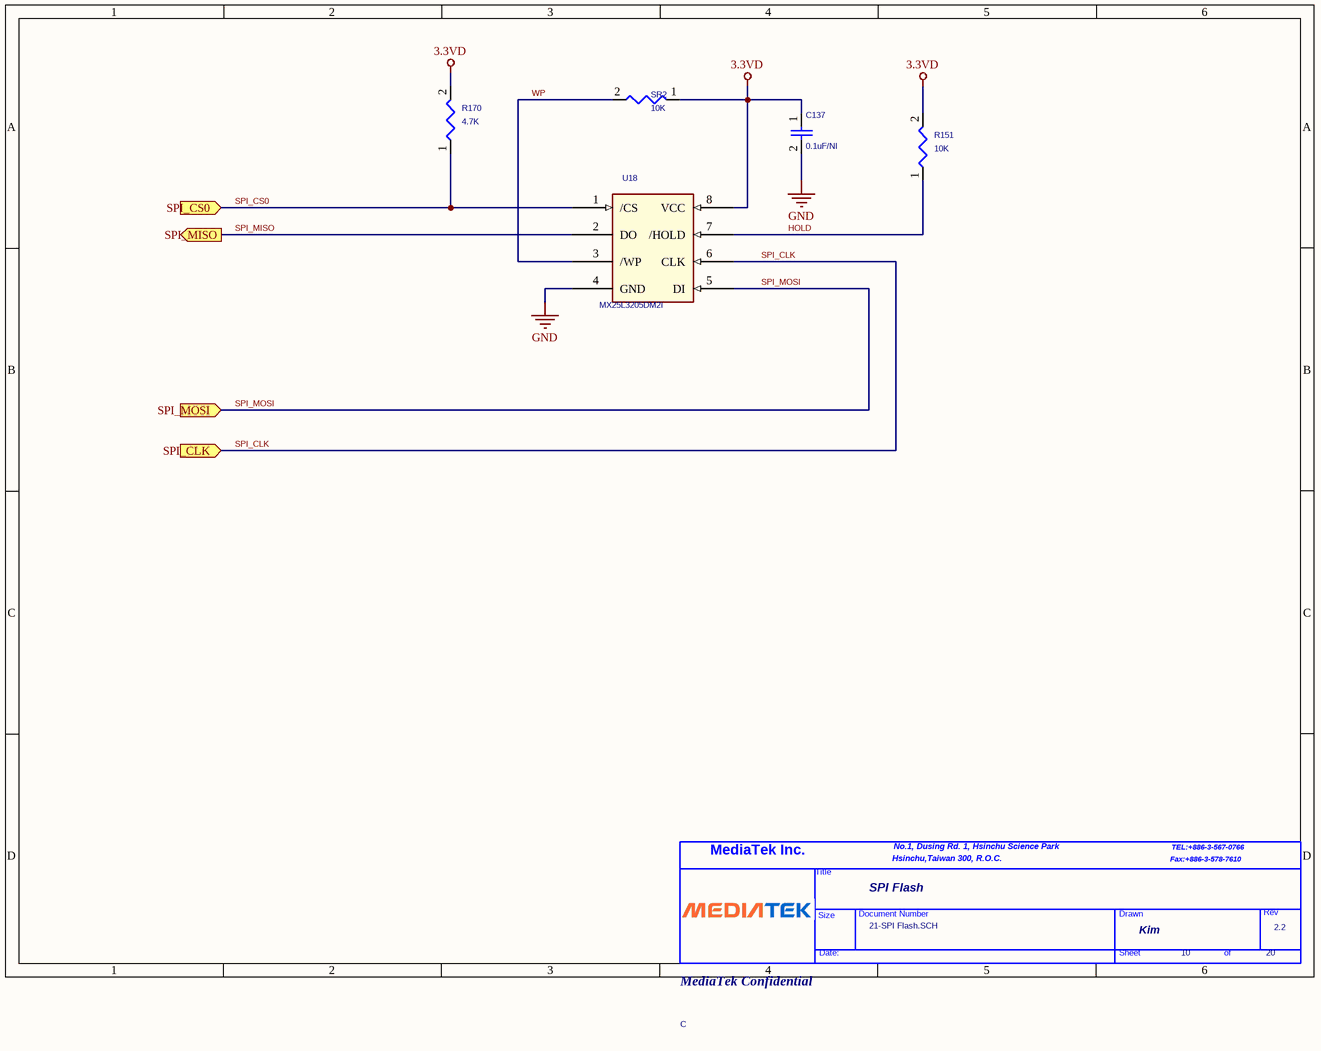
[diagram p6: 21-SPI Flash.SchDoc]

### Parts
(Parts that share a designator on the sheet are numbered #1, #2 ... from top to bottom, then left to right.)
*#5  PIM: MediaTek Confidential  Page Count: 20  Page Number: 10  Page Size: C  Title: SPI Flash  RevCode: 2.2  Doc: 21-SPI Flash.SCH  Designer: Kim  (hidden comment: TitleBlock_MTK4)  (graphical)
C137  0.1uF/NI  [C0402]
R151  10K  [R0402]
R170  4.7K  [R0402]
SR2  10K  [R0402]
U18  MX25L3205DM2I  [SOIC8/SMD/P1.27/AT26DF321]

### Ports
SPI_CLK (in), SPI_CS0 (in), SPI_MISO (out), SPI_MOSI (in)

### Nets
3.3VD: C137.1 R151.2 R170.2 SR2.1 U18.8(VCC)
GND: C137.2 U18.4(GND)
HOLD: R151.1 U18.7(/HOLD)
SPI_CLK: U18.6(CLK) ; port SPI_CLK
SPI_CS0: R170.1 U18.1(/CS) ; port SPI_CS0
SPI_MISO: U18.2(DO) ; port SPI_MISO
SPI_MOSI: U18.5(DI) ; port SPI_MOSI
WP: SR2.2 U18.3(/WP)

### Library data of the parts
C137 = CAP/0402_1
R151 R170 SR2 = RES/0402_3
U18 = SPIFlash-Winbond25P16_0

## Sheet 32-RT5592EP-solt-5G.SchDoc
size 246 x 182 mm
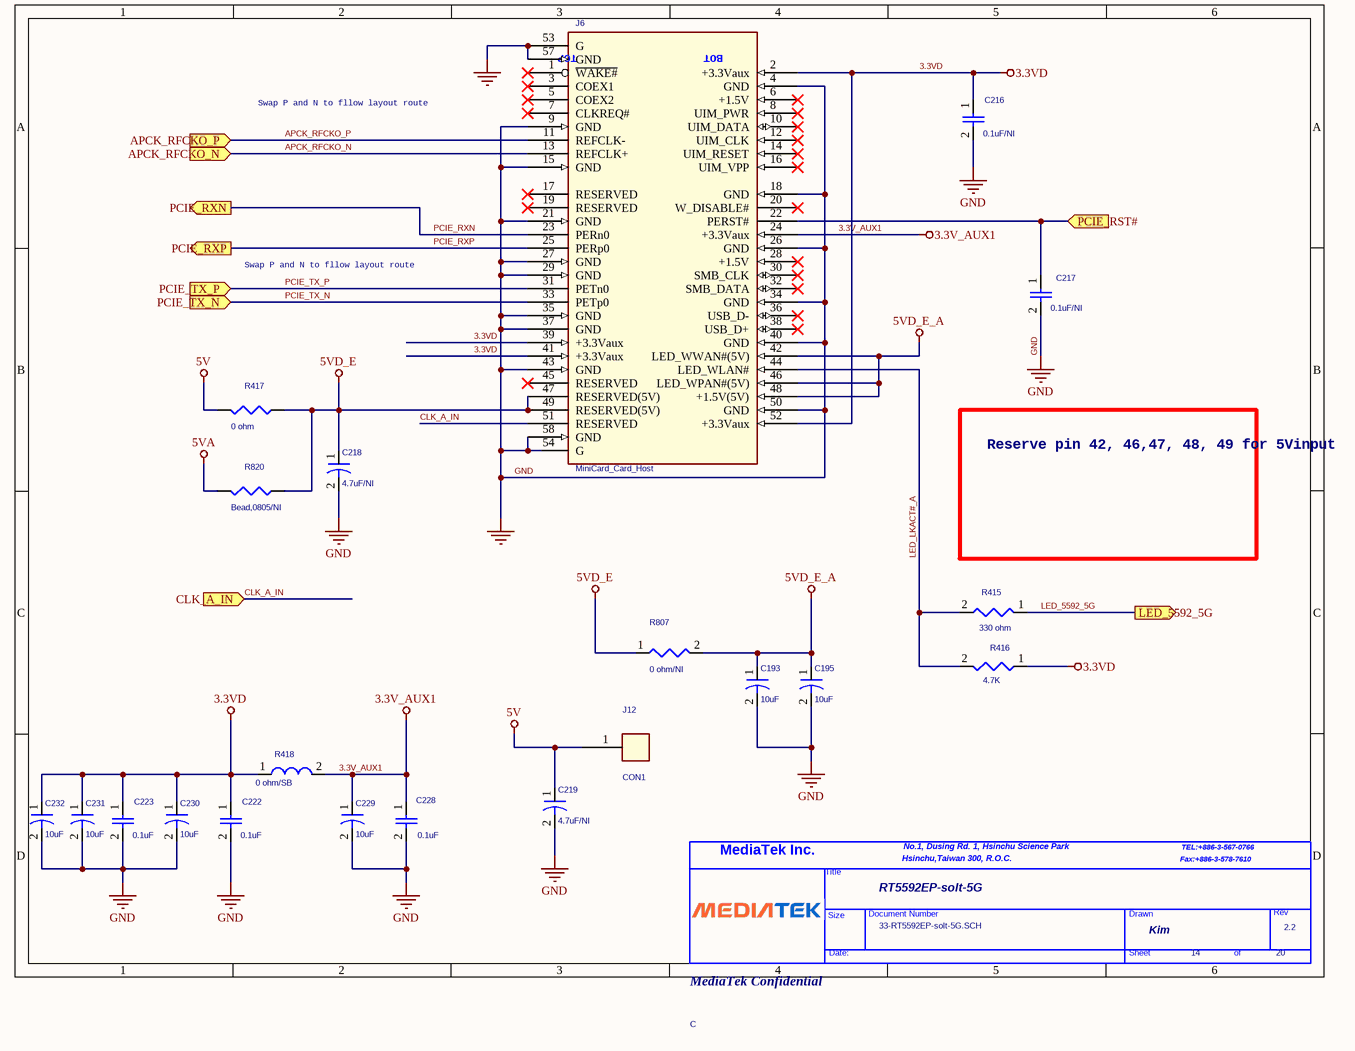
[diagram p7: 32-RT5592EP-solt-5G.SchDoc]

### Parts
(Parts that share a designator on the sheet are numbered #1, #2 ... from top to bottom, then left to right.)
*#6  PIM: MediaTek Confidential  Page Count: 20  Page Number: 14  Page Size: C  Title: RT5592EP-solt-5G  RevCode: 2.2  Doc: 33-RT5592EP-solt-5G.SCH  Designer: Kim  (hidden comment: TitleBlock_MTK4)  (graphical)
C193  10uF  [C0805]
C195  10uF  [C0805]
C216  0.1uF/NI  [C0402]
C217  0.1uF/NI  [C0402]
C218  4.7uF/NI  [C0805]
C219  4.7uF/NI  [C0805]
C222  0.1uF  [C0402]
C223  0.1uF  [C0402]
C228  0.1uF  [C0402]
C229  10uF  [C0805]
C230  10uF  [C0805]
C231  10uF  [C0805]
C232  10uF  [C0805]
J6  MiniCard_Card_Host  [MINI-PCI-Express/52P/SMD/R/F/C1720007]
J12  CON1  [P1//M]
R415  330 ohm  [R0402]
R416  4.7K  [R0402]
R417  0 ohm  [L0805]
R418  0 ohm/SB  [SB/0603]
R807  0 ohm/NI  [C1206]
R820  Bead,0805/NI  [L0805]

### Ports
APCK_RFCKO_N (in), APCK_RFCKO_P (in), CLK_A_IN (in), LED_5592_5G (out), PCIE_RST# (in), PCIE_RXN (out), PCIE_RXP (out), PCIE_TX_N (in), PCIE_TX_P (in)

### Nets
3.3V_AUX1: C228.1 C229.1 J6.24(+3.3Vaux) R418.2
3.3VD: C216.1 C222.1 C223.1 C230.1 C231.1 C232.1 J6.2(+3.3Vaux) J6.39(+3.3Vaux) J6.41(+3.3Vaux) J6.52(+3.3Vaux) R416.1 R418.1
5V: C219.1 J12.1 R417.2
5VA: R820.2
5VD_E: C218.1 J6.47(RESERVED(5V)) J6.49(RESERVED(5V)) R417.1 R807.1 R820.1
5VD_E_A: C193.1 C195.1 J6.42(LED_WWAN#(5V)) J6.46(LED_WPAN#(5V)) J6.48(+1.5V(5V)) R807.2
GND: C193.2 C195.2 C216.2 C217.2 C218.2 C219.2 C222.2 C223.2 C228.2 C229.2 C230.2 C231.2 C232.2 J6.4(GND) J6.9(GND) J6.15(GND) J6.18(GND) J6.21(GND) J6.26(GND) J6.27(GND) J6.29(GND) J6.34(GND) J6.35(GND) J6.37(GND) J6.40(GND) J6.43(GND) J6.50(GND) J6.53(G) J6.54(G) J6.57(GND) J6.58(GND)
APCK_RFCKO_N: J6.13(REFCLK+) ; port APCK_RFCKO_N
APCK_RFCKO_P: J6.11(REFCLK-) ; port APCK_RFCKO_P
CLK_A_IN: J6.51(RESERVED) ; port CLK_A_IN
LED_5592_5G: R415.1 ; port LED_5592_5G
LED_LKACT#_A: J6.44(LED_WLAN#) R415.2 R416.2
PCIE_RST#: C217.1 J6.22(PERST#) ; port PCIE_RST#
PCIE_RXN: J6.23(PERn0) ; port PCIE_RXN
PCIE_RXP: J6.25(PERp0) ; port PCIE_RXP
PCIE_TX_N: J6.33(PETp0) ; port PCIE_TX_N
PCIE_TX_P: J6.31(PETn0) ; port PCIE_TX_P

Not connected (* = marked no-connect by the designer): J6 1(~{WAKE#})* 3(COEX1)* 5(COEX2)* 6(+1.5V)* 7(CLKREQ#)* 8(UIM_PWR)* 10(UIM_DATA)* 12(UIM_CLK)* 14(UIM_RESET)* 16(UIM_VPP)* 17(RESERVED)* 19(RESERVED)* 20(W_DISABLE#)* 28(+1.5V)* 30(SMB_CLK)* 32(SMB_DATA)* 36(USB_D-)* 38(USB_D+)* 45(RESERVED)*

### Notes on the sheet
- Swap P and N to fllow layout route
- Reserve pin 42, 46,47, 48, 49 for 5Vinput

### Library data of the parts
C193 C195 C218 C219 = CAP/1210_1206
C216 C217 C222 C223 C228 = CAP/0402_Dup2: 1st Part Field: 0402
C229-C232 = CAP/0805
J6 = MiniCard_Card_Host_V12_0
R415 R416 = RES/0402_1
R417 R820 = R: Resistor, 0603, 5%; Part Number: 110-110-00100; Manufacturer: �j驾�歆�; Class: 1R-0402; Key: 3162U-N14-V11-#449; SDTSourceLibName: C:\WINDOWS\TEMP\2GM.LIB; V1: 25V 20%; By: Ralink; HYP_Type: (R; BOM_Class: Chipset
R418 = L/1206_0805
R807 = RES/1206_0805

## Sheet 31-Antenna.SchDoc
size 386 x 246 mm
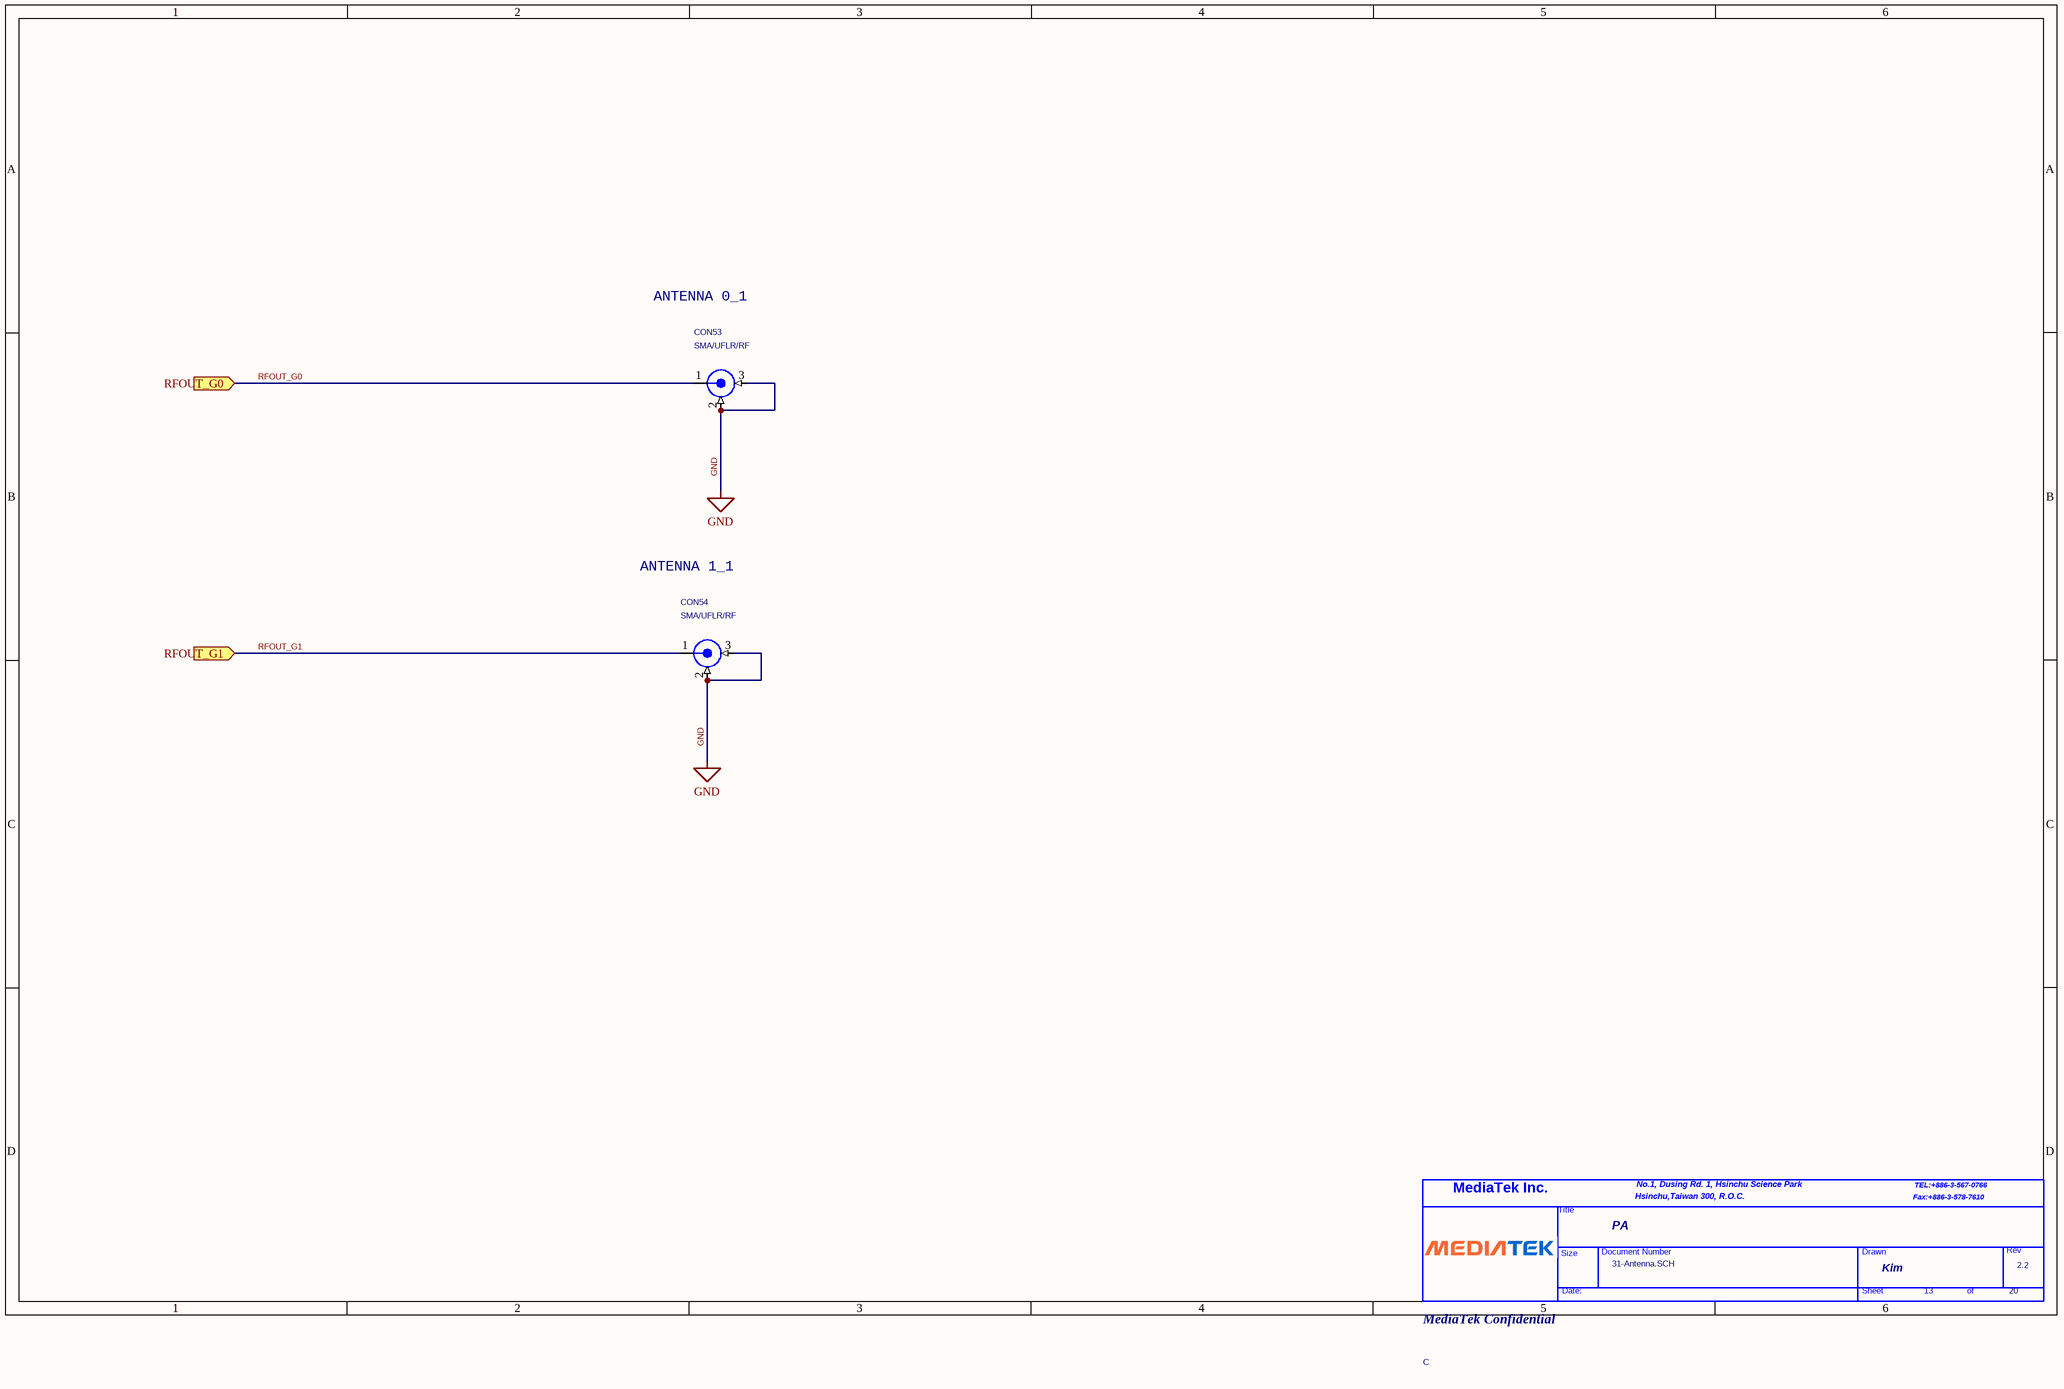
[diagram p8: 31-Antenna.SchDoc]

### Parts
(Parts that share a designator on the sheet are numbered #1, #2 ... from top to bottom, then left to right.)
*#7  PIM: MediaTek Confidential  Page Count: 20  Page Number: 13  Page Size: C  Title: PA  RevCode: 2.2  Doc: 31-Antenna.SCH  Designer: Kim  (hidden comment: TitleBlock_MTK4)  (graphical)
CON53  SMA/UFLR/RF  [COAXIAL/SMD/CON/V/I-PEX/W08-5801]
CON54  SMA/UFLR/RF  [COAXIAL/SMD/CON/V/I-PEX/W08-5801]

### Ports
RFOUT_G0 (in), RFOUT_G1 (in)

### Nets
GND: CON53.2 CON53.3(GNDA) CON54.2 CON54.3(GNDA)
RFOUT_G0: CON53.1 ; port RFOUT_G0
RFOUT_G1: CON54.1 ; port RFOUT_G1

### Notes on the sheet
- ANTENNA 0_1
- ANTENNA 1_1

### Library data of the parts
CON53 CON54 = SMA/UFLR

## Sheet 43-GE2-XMER-RJ45.SchDoc
size 386 x 259 mm
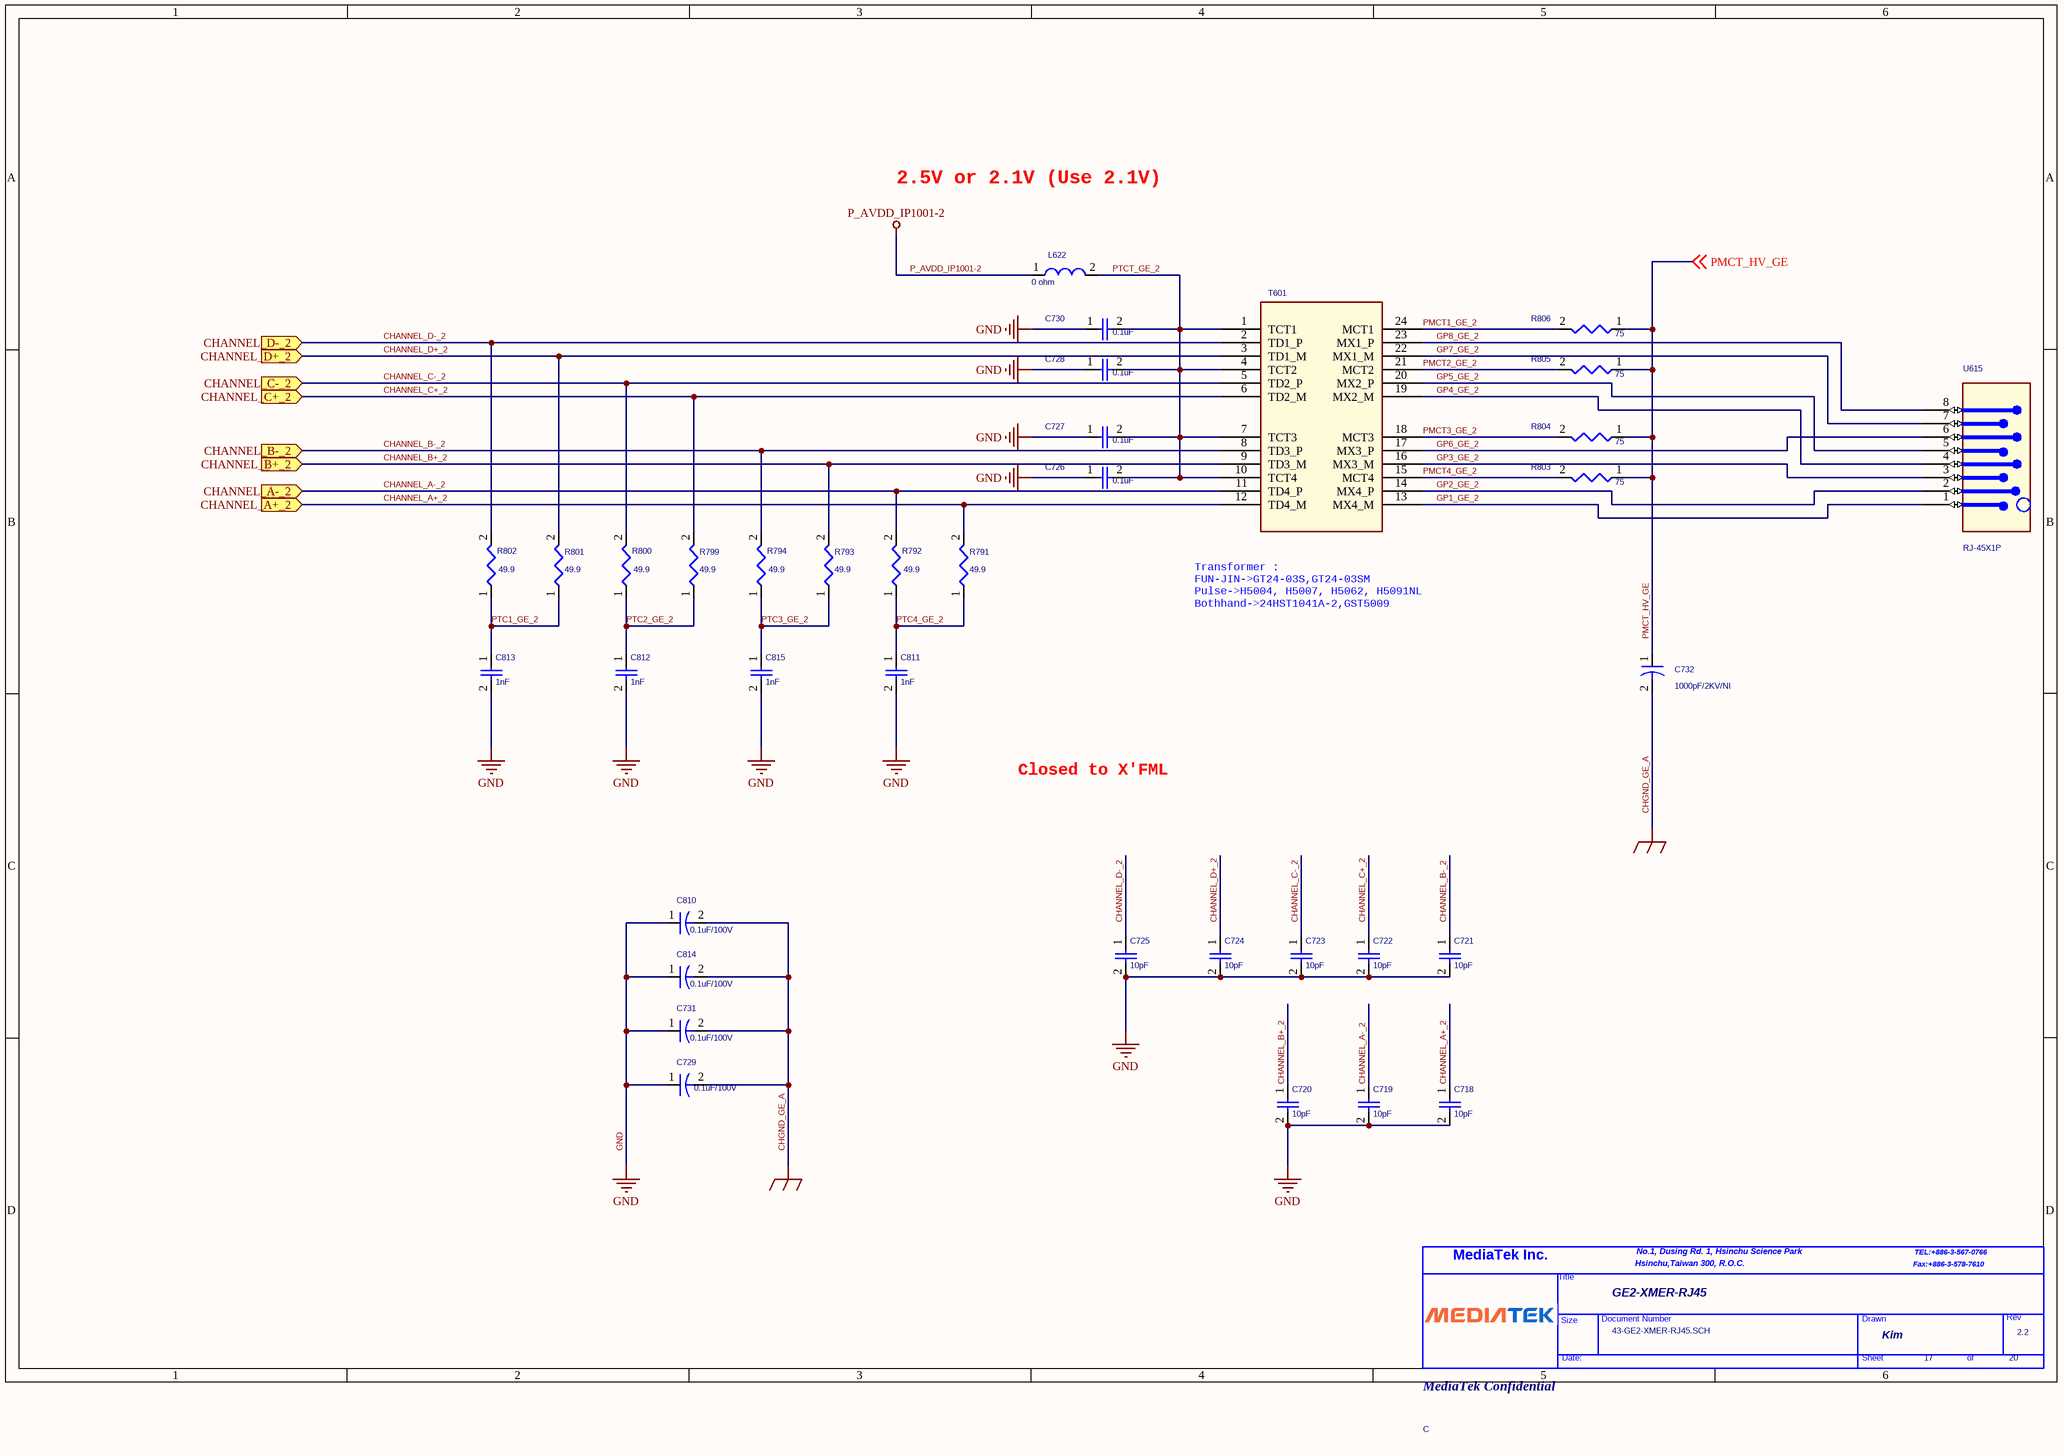
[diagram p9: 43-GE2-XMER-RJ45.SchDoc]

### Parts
(Parts that share a designator on the sheet are numbered #1, #2 ... from top to bottom, then left to right.)
*#8  PIM: MediaTek Confidential  Page Count: 20  Page Number: 17  Page Size: C  Title: GE2-XMER-RJ45  RevCode: 2.2  Doc: 43-GE2-XMER-RJ45.SCH  Designer: Kim  (hidden comment: TitleBlock_MTK4)  (graphical)
C718  10pF  [C0402]
C719  10pF  [C0402]
C720  10pF  [C0402]
C721  10pF  [C0402]
C722  10pF  [C0402]
C723  10pF  [C0402]
C724  10pF  [C0402]
C725  10pF  [C0402]
C726  0.1uF  [C0402]
C727  0.1uF  [C0402]
C728  0.1uF  [C0402]
C729  0.1uF/100V  [SB/1206]
C730  0.1uF  [C0402]
C731  0.1uF/100V  [SB/1206]
C732  1000pF/2KV/NI  [C1206]
C810  0.1uF/100V  [SB/1206]
C811  1nF  [C0402]
C812  1nF  [C0402]
C813  1nF  [C0402]
C814  0.1uF/100V  [SB/1206]
C815  1nF  [C0402]
L622  0 ohm  [L0805]
R791  49.9  [R0402]
R792  49.9  [R0402]
R793  49.9  [R0402]
R794  49.9  [R0402]
R799  49.9  [R0402]
R800  49.9  [R0402]
R801  49.9  [R0402]
R802  49.9  [R0402]
R803  75  [R0402]
R804  75  [R0402]
R805  75  [R0402]
R806  75  [R0402]
T601  FT20-252B  [TRANSFORMER/24P/SMD/HN2429CG]  (value not drawn)
U615  RJ-45X1P  [RJ45/8P/DIP/R/8208C-B01]

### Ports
CHANNEL_A+_2 (in), CHANNEL_A-_2 (in), CHANNEL_B+_2 (in), CHANNEL_B-_2 (in), CHANNEL_C+_2 (in), CHANNEL_C-_2 (in), CHANNEL_D+_2 (in), CHANNEL_D-_2 (in)

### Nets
CHGND_GE_A: C729.2 C731.2 C732.2 C810.2 C814.2
GND: C718.2 C719.2 C720.2 C721.2 C722.2 C723.2 C724.2 C725.2 C726.1 C727.1 C728.1 C729.1 C730.1 C731.1 C810.1 C811.2 C812.2 C813.2 C814.1 C815.2
P_AVDD_IP1001-2: L622.1
CHANNEL_A+_2: C718.1 R791.2 T601.12(TD4_M) ; port CHANNEL_A+_2
CHANNEL_A-_2: C719.1 R792.2 T601.11(TD4_P) ; port CHANNEL_A-_2
CHANNEL_B+_2: C720.1 R793.2 T601.9(TD3_M) ; port CHANNEL_B+_2
CHANNEL_B-_2: C721.1 R794.2 T601.8(TD3_P) ; port CHANNEL_B-_2
CHANNEL_C+_2: C722.1 R799.2 T601.6(TD2_M) ; port CHANNEL_C+_2
CHANNEL_C-_2: C723.1 R800.2 T601.5(TD2_P) ; port CHANNEL_C-_2
CHANNEL_D+_2: C724.1 R801.2 T601.3(TD1_M) ; port CHANNEL_D+_2
CHANNEL_D-_2: C725.1 R802.2 T601.2(TD1_P) ; port CHANNEL_D-_2
GP1_GE_2: T601.13(MX4_M) U615.1(P1)
GP2_GE_2: T601.14(MX4_P) U615.2(P2)
GP3_GE_2: T601.16(MX3_M) U615.3(P3)
GP4_GE_2: T601.19(MX2_M) U615.4(P4)
GP5_GE_2: T601.20(MX2_P) U615.5(P5)
GP6_GE_2: T601.17(MX3_P) U615.6(P6)
GP7_GE_2: T601.22(MX1_M) U615.7(P7)
GP8_GE_2: T601.23(MX1_P) U615.8(P8)
PMCT1_GE_2: R806.2 T601.24(MCT1)
PMCT2_GE_2: R805.2 T601.21(MCT2)
PMCT3_GE_2: R804.2 T601.18(MCT3)
PMCT4_GE_2: R803.2 T601.15(MCT4)
PMCT_HV_GE: C732.1 R803.1 R804.1 R805.1 R806.1 ; off-sheet PMCT_HV_GE
PTC1_GE_2: C813.1 R801.1 R802.1
PTC2_GE_2: C812.1 R799.1 R800.1
PTC3_GE_2: C815.1 R793.1 R794.1
PTC4_GE_2: C811.1 R791.1 R792.1
PTCT_GE_2: C726.2 C727.2 C728.2 C730.2 L622.2 T601.1(TCT1) T601.4(TCT2) T601.7(TCT3) T601.10(TCT4)

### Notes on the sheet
- 2.5V or 2.1V (Use 2.1V)
- Transformer :
  FUN-JIN->GT24-03S,GT24-03SM
  Pulse->H5004, H5007, H5062, H5091NL
  Bothhand->24HST1041A-2,GST5009
- Closed to X'FML

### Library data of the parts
C718-C728 C730 C811-C813 C815 = CAP/0402_Dup2
C729 C731 C810 C814 = CAP/1206
C732 = CAP/1206_Dup1
L622 = L/0805_0603
R791-R794 R799-R806 = RES/0402_Dup2
T601 = FT20-252B_2
U615 = RJ-45X1P-NO-SH

## Sheet 42-GE-XMER-RJ45.SchDoc
size 386 x 259 mm
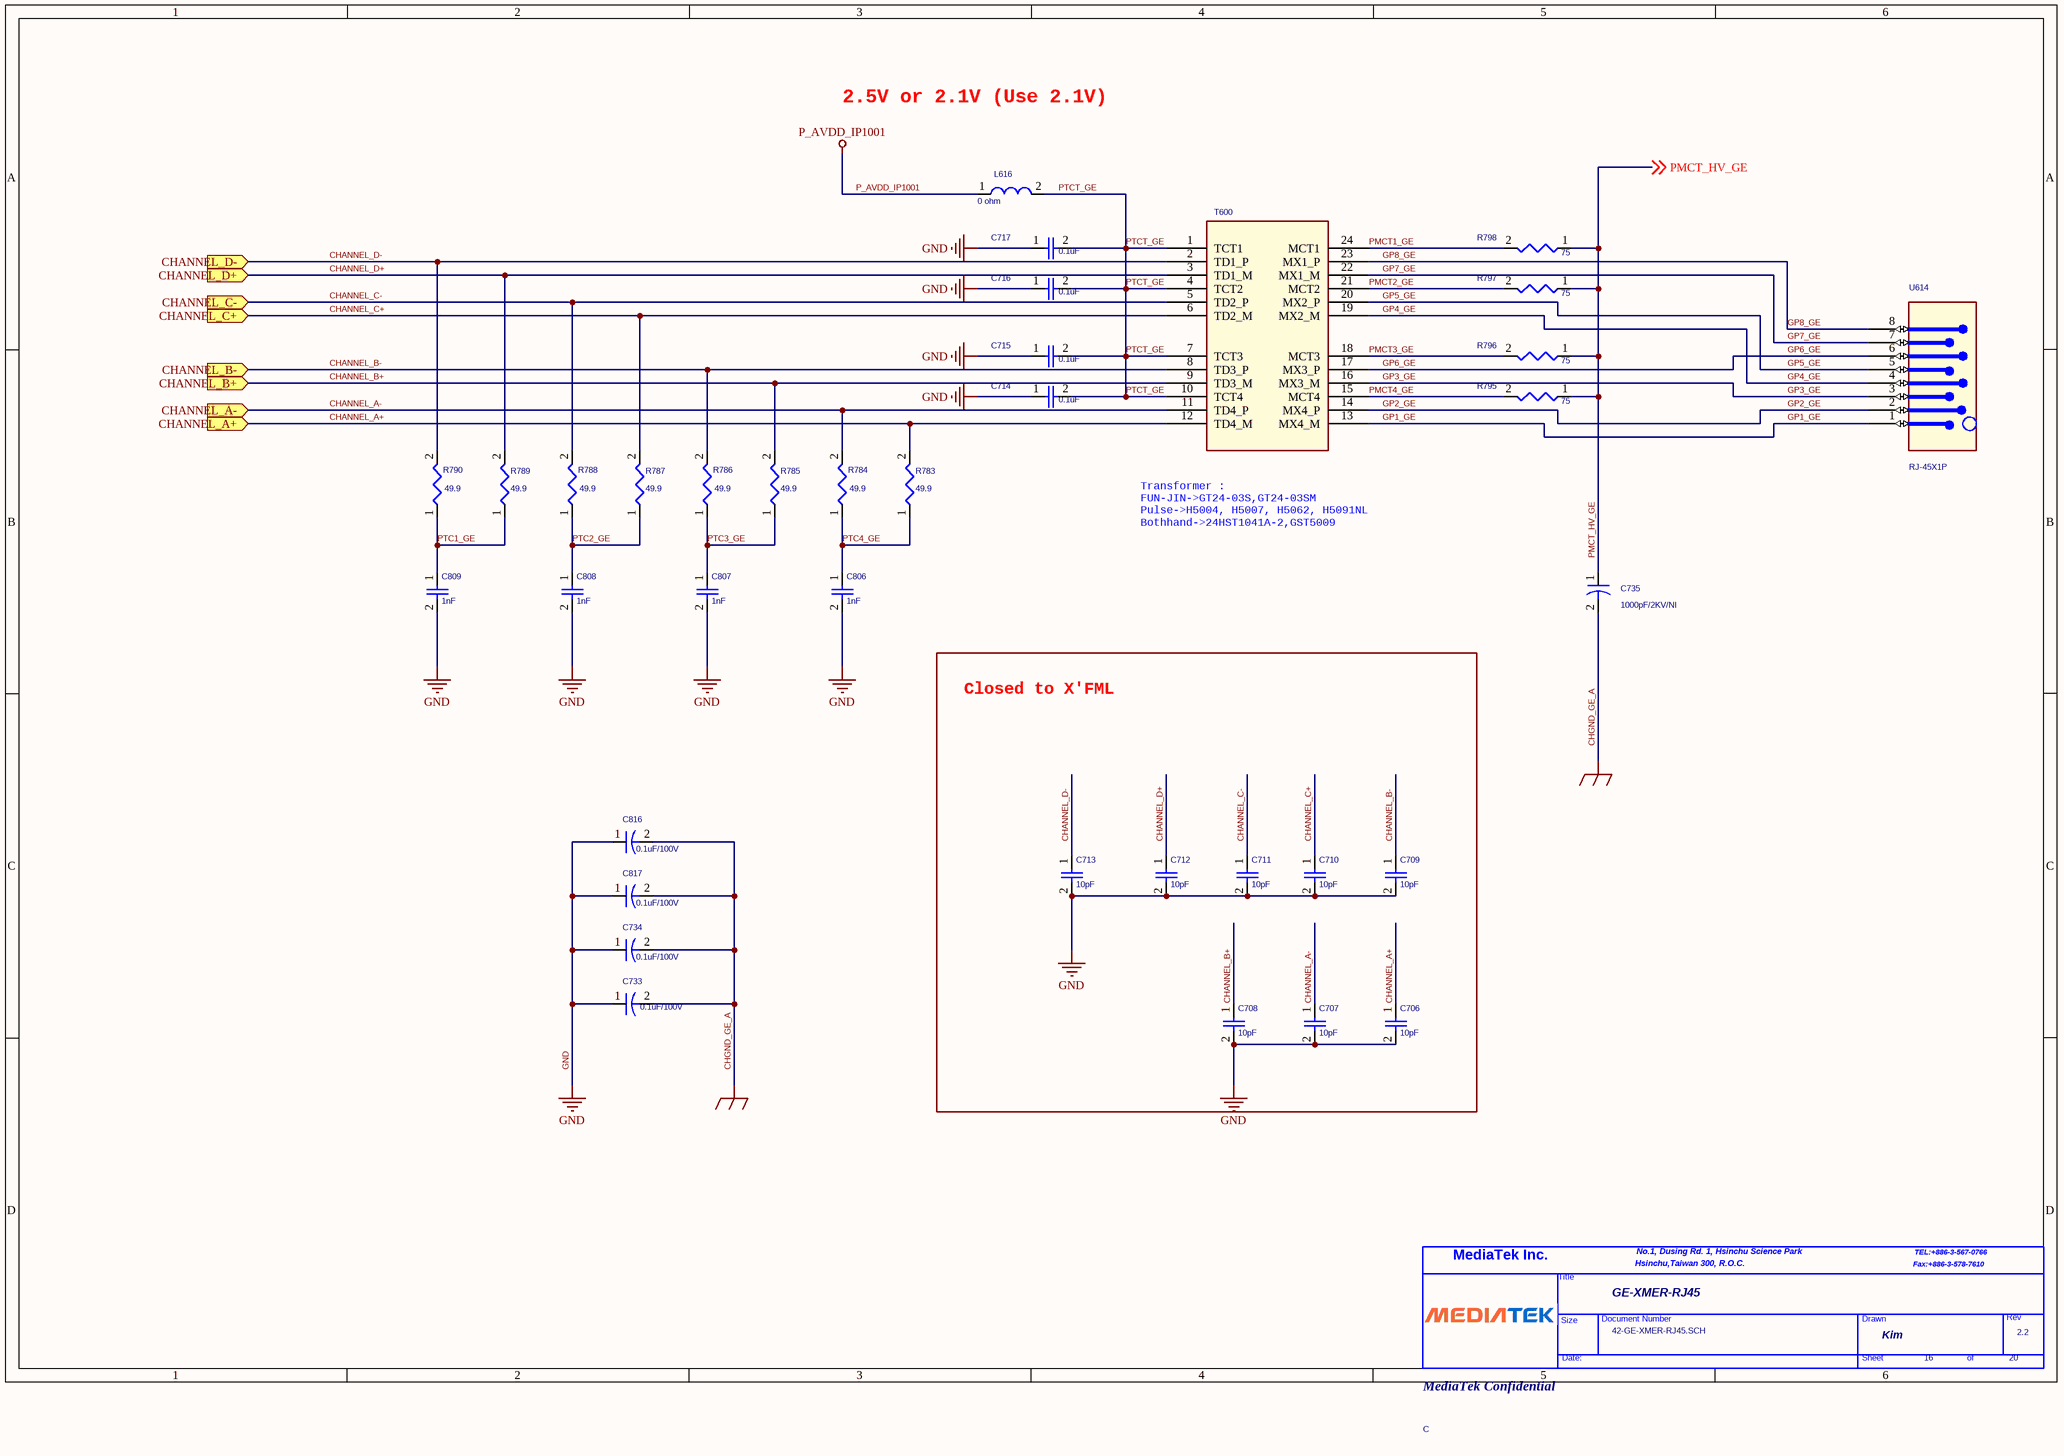
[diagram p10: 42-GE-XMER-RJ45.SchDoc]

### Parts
(Parts that share a designator on the sheet are numbered #1, #2 ... from top to bottom, then left to right.)
*#9  PIM: MediaTek Confidential  Page Count: 20  Page Number: 16  Page Size: C  Title: GE-XMER-RJ45  RevCode: 2.2  Doc: 42-GE-XMER-RJ45.SCH  Designer: Kim  (hidden comment: TitleBlock_MTK4)  (graphical)
C706  10pF  [C0402]
C707  10pF  [C0402]
C708  10pF  [C0402]
C709  10pF  [C0402]
C710  10pF  [C0402]
C711  10pF  [C0402]
C712  10pF  [C0402]
C713  10pF  [C0402]
C714  0.1uF  [C0402]
C715  0.1uF  [C0402]
C716  0.1uF  [C0402]
C717  0.1uF  [C0402]
C733  0.1uF/100V  [SB/1206]
C734  0.1uF/100V  [SB/1206]
C735  1000pF/2KV/NI  [C1206]
C806  1nF  [C0402]
C807  1nF  [C0402]
C808  1nF  [C0402]
C809  1nF  [C0402]
C816  0.1uF/100V  [SB/1206]
C817  0.1uF/100V  [SB/1206]
L616  0 ohm  [L0805]
R783  49.9  [R0402]
R784  49.9  [R0402]
R785  49.9  [R0402]
R786  49.9  [R0402]
R787  49.9  [R0402]
R788  49.9  [R0402]
R789  49.9  [R0402]
R790  49.9  [R0402]
R795  75  [R0402]
R796  75  [R0402]
R797  75  [R0402]
R798  75  [R0402]
T600  FT20-252B  [TRANSFORMER/24P/SMD/HN2429CG]  (value not drawn)
U614  RJ-45X1P  [RJ45/8P/DIP/R/8208C-B01]

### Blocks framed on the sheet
Closed to X'FML: C706-C713

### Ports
CHANNEL_A+ (in), CHANNEL_A- (in), CHANNEL_B+ (in), CHANNEL_B- (in), CHANNEL_C+ (in), CHANNEL_C- (in), CHANNEL_D+ (in), CHANNEL_D- (in)

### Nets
CHGND_GE_A: C733.2 C734.2 C735.2 C816.2 C817.2
GND: C706.2 C707.2 C708.2 C709.2 C710.2 C711.2 C712.2 C713.2 C714.1 C715.1 C716.1 C717.1 C733.1 C734.1 C806.2 C807.2 C808.2 C809.2 C816.1 C817.1
P_AVDD_IP1001: L616.1
CHANNEL_A+: C706.1 R783.2 T600.12(TD4_M) ; port CHANNEL_A+
CHANNEL_A-: C707.1 R784.2 T600.11(TD4_P) ; port CHANNEL_A-
CHANNEL_B+: C708.1 R785.2 T600.9(TD3_M) ; port CHANNEL_B+
CHANNEL_B-: C709.1 R786.2 T600.8(TD3_P) ; port CHANNEL_B-
CHANNEL_C+: C710.1 R787.2 T600.6(TD2_M) ; port CHANNEL_C+
CHANNEL_C-: C711.1 R788.2 T600.5(TD2_P) ; port CHANNEL_C-
CHANNEL_D+: C712.1 R789.2 T600.3(TD1_M) ; port CHANNEL_D+
CHANNEL_D-: C713.1 R790.2 T600.2(TD1_P) ; port CHANNEL_D-
GP1_GE: T600.13(MX4_M) U614.1(P1)
GP2_GE: T600.14(MX4_P) U614.2(P2)
GP3_GE: T600.16(MX3_M) U614.3(P3)
GP4_GE: T600.19(MX2_M) U614.4(P4)
GP5_GE: T600.20(MX2_P) U614.5(P5)
GP6_GE: T600.17(MX3_P) U614.6(P6)
GP7_GE: T600.22(MX1_M) U614.7(P7)
GP8_GE: T600.23(MX1_P) U614.8(P8)
PMCT1_GE: R798.2 T600.24(MCT1)
PMCT2_GE: R797.2 T600.21(MCT2)
PMCT3_GE: R796.2 T600.18(MCT3)
PMCT4_GE: R795.2 T600.15(MCT4)
PMCT_HV_GE: C735.1 R795.1 R796.1 R797.1 R798.1 ; off-sheet PMCT_HV_GE
PTC1_GE: C809.1 R789.1 R790.1
PTC2_GE: C808.1 R787.1 R788.1
PTC3_GE: C807.1 R785.1 R786.1
PTC4_GE: C806.1 R783.1 R784.1
PTCT_GE: C714.2 C715.2 C716.2 C717.2 L616.2 T600.1(TCT1) T600.4(TCT2) T600.7(TCT3) T600.10(TCT4)

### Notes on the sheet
- 2.5V or 2.1V (Use 2.1V)
- Transformer :
  FUN-JIN->GT24-03S,GT24-03SM
  Pulse->H5004, H5007, H5062, H5091NL
  Bothhand->24HST1041A-2,GST5009

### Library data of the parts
C706-C717 C806-C809 = CAP/0402_Dup2
C733 C734 C816 C817 = CAP/1206
C735 = CAP/1206_Dup1
L616 = L/0805_0603
R783-R790 R795-R798 = RES/0402_Dup2
T600 = FT20-252B_2
U614 = RJ-45X1P-NO-SH

## Sheet 41-XMER-RJ45.SchDoc
size 513 x 386 mm
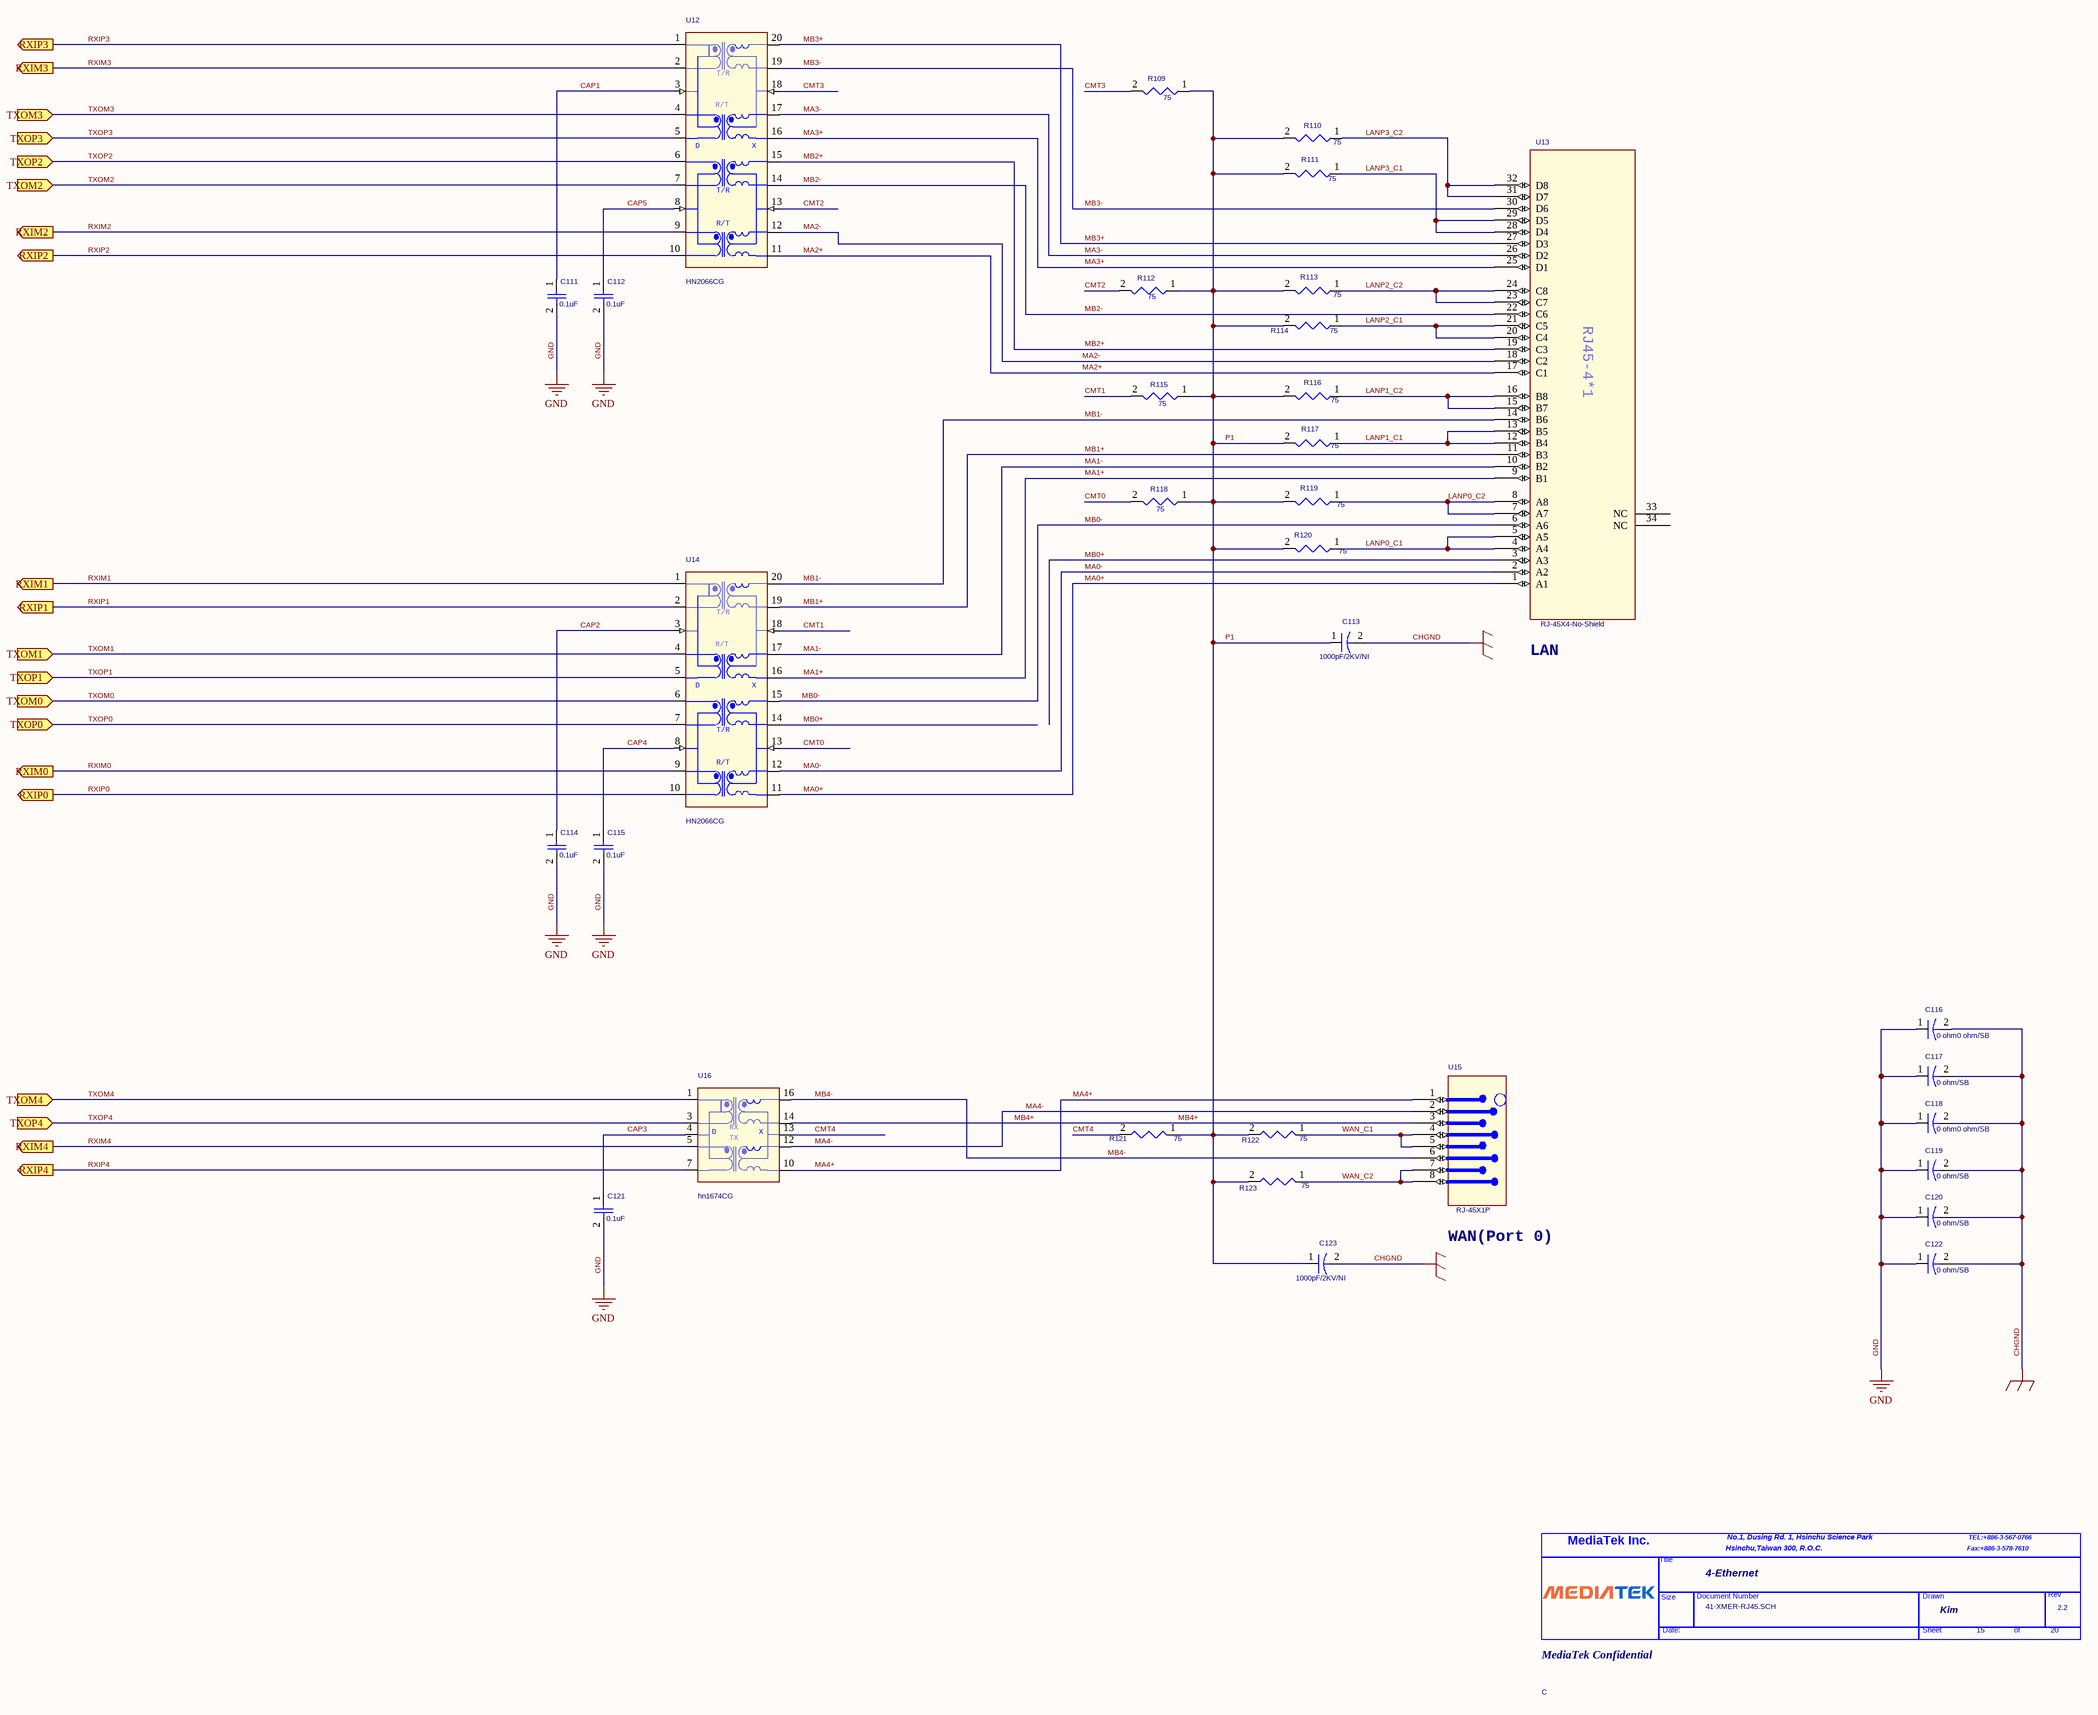
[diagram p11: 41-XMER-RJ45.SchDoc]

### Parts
(Parts that share a designator on the sheet are numbered #1, #2 ... from top to bottom, then left to right.)
*#10  PIM: MediaTek Confidential  Page Count: 20  Page Number: 15  Page Size: C  Title: 4-Ethernet  RevCode: 2.2  Doc: 41-XMER-RJ45.SCH  Designer: Kim  (hidden comment: TitleBlock_MTK4)  (graphical)
C111  0.1uF  [C0402]
C112  0.1uF  [C0402]
C113  1000pF/2KV/NI  [C1206]
C114  0.1uF  [C0402]
C115  0.1uF  [C0402]
C116  0 ohm0 ohm/SB  [SB/1206]
C117  0 ohm/SB  [SB/1206]
C118  0 ohm0 ohm/SB  [SB/1206]
C119  0 ohm/SB  [SB/1206]
C120  0 ohm/SB  [SB/1206]
C121  0.1uF  [C0402]
C122  0 ohm/SB  [SB/1206]
C123  1000pF/2KV/NI  [C1206]
R109  75  [R0402]
R110  75  [R0402]
R111  75  [R0402]
R112  75  [R0402]
R113  75  [R0402]
R114  75  [R0402]
R115  75  [R0402]
R116  75  [R0402]
R117  75  [R0402]
R118  75  [R0402]
R119  75  [R0402]
R120  75  [R0402]
R121  75  [R0402]
R122  75  [R0402]
R123  75  [R0402]
U12  HN2066CG  [TRANSFORMER/20P/DIP/HN2066CG]
U13  RJ-45X4-No-Shield  [RJ45/32P/DIP/R/N3642-001]
U14  HN2066CG  [TRANSFORMER/20P/DIP/HN2066CG]
U15  RJ-45X1P  [RJ45/8P/DIP/R/N3612-002]
U16  hn1674CG  [TRANSFORMER/16P/DIP/HN1674CG]

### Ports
RXIM0 (out), RXIM1 (out), RXIM2 (out), RXIM3 (out), RXIM4 (out), RXIP0 (out), RXIP1 (out), RXIP2 (out), RXIP3 (out), RXIP4 (out), TXOM0 (in), TXOM1 (in), TXOM2 (in), TXOM3 (in), TXOM4 (in), TXOP0 (in), TXOP1 (in), TXOP2 (in), TXOP3 (in), TXOP4 (in)

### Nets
CHGND: C113.2 C116.2 C117.2 C118.2 C119.2 C120.2 C122.2 C123.2
GND: C111.2 C112.2 C114.2 C115.2 C116.1 C117.1 C118.1 C119.1 C120.1 C121.2 C122.1
CAP1: C111.1 U12.3(CT1)
CAP2: C114.1 U14.3(CT1)
CAP3: C121.1 U16.4(CT)
CAP4: C115.1 U14.8(CT2)
CAP5: C112.1 U12.8(CT2)
CMT0: R118.2 U14.13(CTX2)
CMT1: R115.2 U14.18(CTX1)
CMT2: R112.2 U12.13(CTX2)
CMT3: R109.2 U12.18(CTX1)
CMT4: R121.2 U16.13(CG)
LANP0_C1: R120.1 U13.4(A4) U13.5(A5)
LANP0_C2: R119.1 U13.7(A7) U13.8(A8)
LANP1_C1: R117.1 U13.12(B4) U13.13(B5)
LANP1_C2: R116.1 U13.15(B7) U13.16(B8)
LANP2_C1: R114.1 U13.20(C4) U13.21(C5)
LANP2_C2: R113.1 U13.23(C7) U13.24(C8)
LANP3_C1: R111.1 U13.28(D4) U13.29(D5)
LANP3_C2: R110.1 U13.31(D7) U13.32(D8)
MA0+: U13.1(A1) U14.11(RTX-2)
MA0-: U13.2(A2) U14.12(RTX+2)
MA1+: U13.9(B1) U14.16(RTX-1)
MA1-: U13.10(B2) U14.17(RTX+1)
MA2+: U12.11(RTX-2) U13.17(C1)
MA2-: U12.12(RTX+2) U13.18(C2)
MA3+: U12.16(RTX-1) U13.25(D1)
MA3-: U12.17(RTX+1) U13.26(D2)
MA4+: U15.1(P1) U16.10(TX-)
MA4-: U15.2(P2) U16.12(TX+)
MB0+: U13.3(A3) U14.14(TRX-1)
MB0-: U13.6(A6) U14.15(TRX+2)
MB1+: U13.11(B3) U14.19(TRX-1)
MB1-: U13.14(B6) U14.20(TRX+1)
MB2+: U12.15(TRX+2) U13.19(C3)
MB2-: U12.14(TRX-1) U13.22(C6)
MB3+: U12.20(TRX+1) U13.27(D3)
MB3-: U12.19(TRX-1) U13.30(D6)
MB4+: U15.3(P3) U16.14(RX-)
MB4-: U15.6(P6) U16.16(RX+)
P1: C113.1 C123.1 R109.1 R110.2 R111.2 R112.1 R113.2 R114.2 R115.1 R116.2 R117.2 R118.1 R119.2 R120.2 R121.1 R122.2 R123.2
RXIM0: U14.9(RTD+2) ; port RXIM0
RXIM1: U14.1(TRD+1) ; port RXIM1
RXIM2: U12.9(RTD+2) ; port RXIM2
RXIM3: U12.2(TRD-1) ; port RXIM3
RXIM4: U16.5(TD+) ; port RXIM4
RXIP0: U14.10(RTD-2) ; port RXIP0
RXIP1: U14.2(TRD-1) ; port RXIP1
RXIP2: U12.10(RTD-2) ; port RXIP2
RXIP3: U12.1(TRD+1) ; port RXIP3
RXIP4: U16.7(TD-) ; port RXIP4
TXOM0: U14.6(TRD+2) ; port TXOM0
TXOM1: U14.4(RTD+1) ; port TXOM1
TXOM2: U12.7(TRD+2) ; port TXOM2
TXOM3: U12.4(RTD+1) ; port TXOM3
TXOM4: U16.1(RD+) ; port TXOM4
TXOP0: U14.7(TRD+2) ; port TXOP0
TXOP1: U14.5(RTD-1) ; port TXOP1
TXOP2: U12.6(TRD+2) ; port TXOP2
TXOP3: U12.5(RTD-1) ; port TXOP3
TXOP4: U16.3(RD-) ; port TXOP4
WAN_C1: R122.1 U15.4(P4) U15.5(P5)
WAN_C2: R123.1 U15.7(P7) U15.8(P8)

Not connected (* = marked no-connect by the designer): U13 33(NC) 34(NC)

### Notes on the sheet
- LAN
- WAN(Port 0)

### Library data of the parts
C111 C112 C114 C115 C121 = CAP/0402
C113 C116-C120 C122 C123 = CAP/1206_Dup1
R109-R123 = RES/0402
U12 U14 = XMER 2P LFE8583_12
U13 = RJ-45X4P-NO-SH
U15 = RJ-45X1P-NO-SH
U16 = XMER 1P LFE8657_5

## Sheet 5-POWER-RESET.SchDoc
size 513 x 386 mm
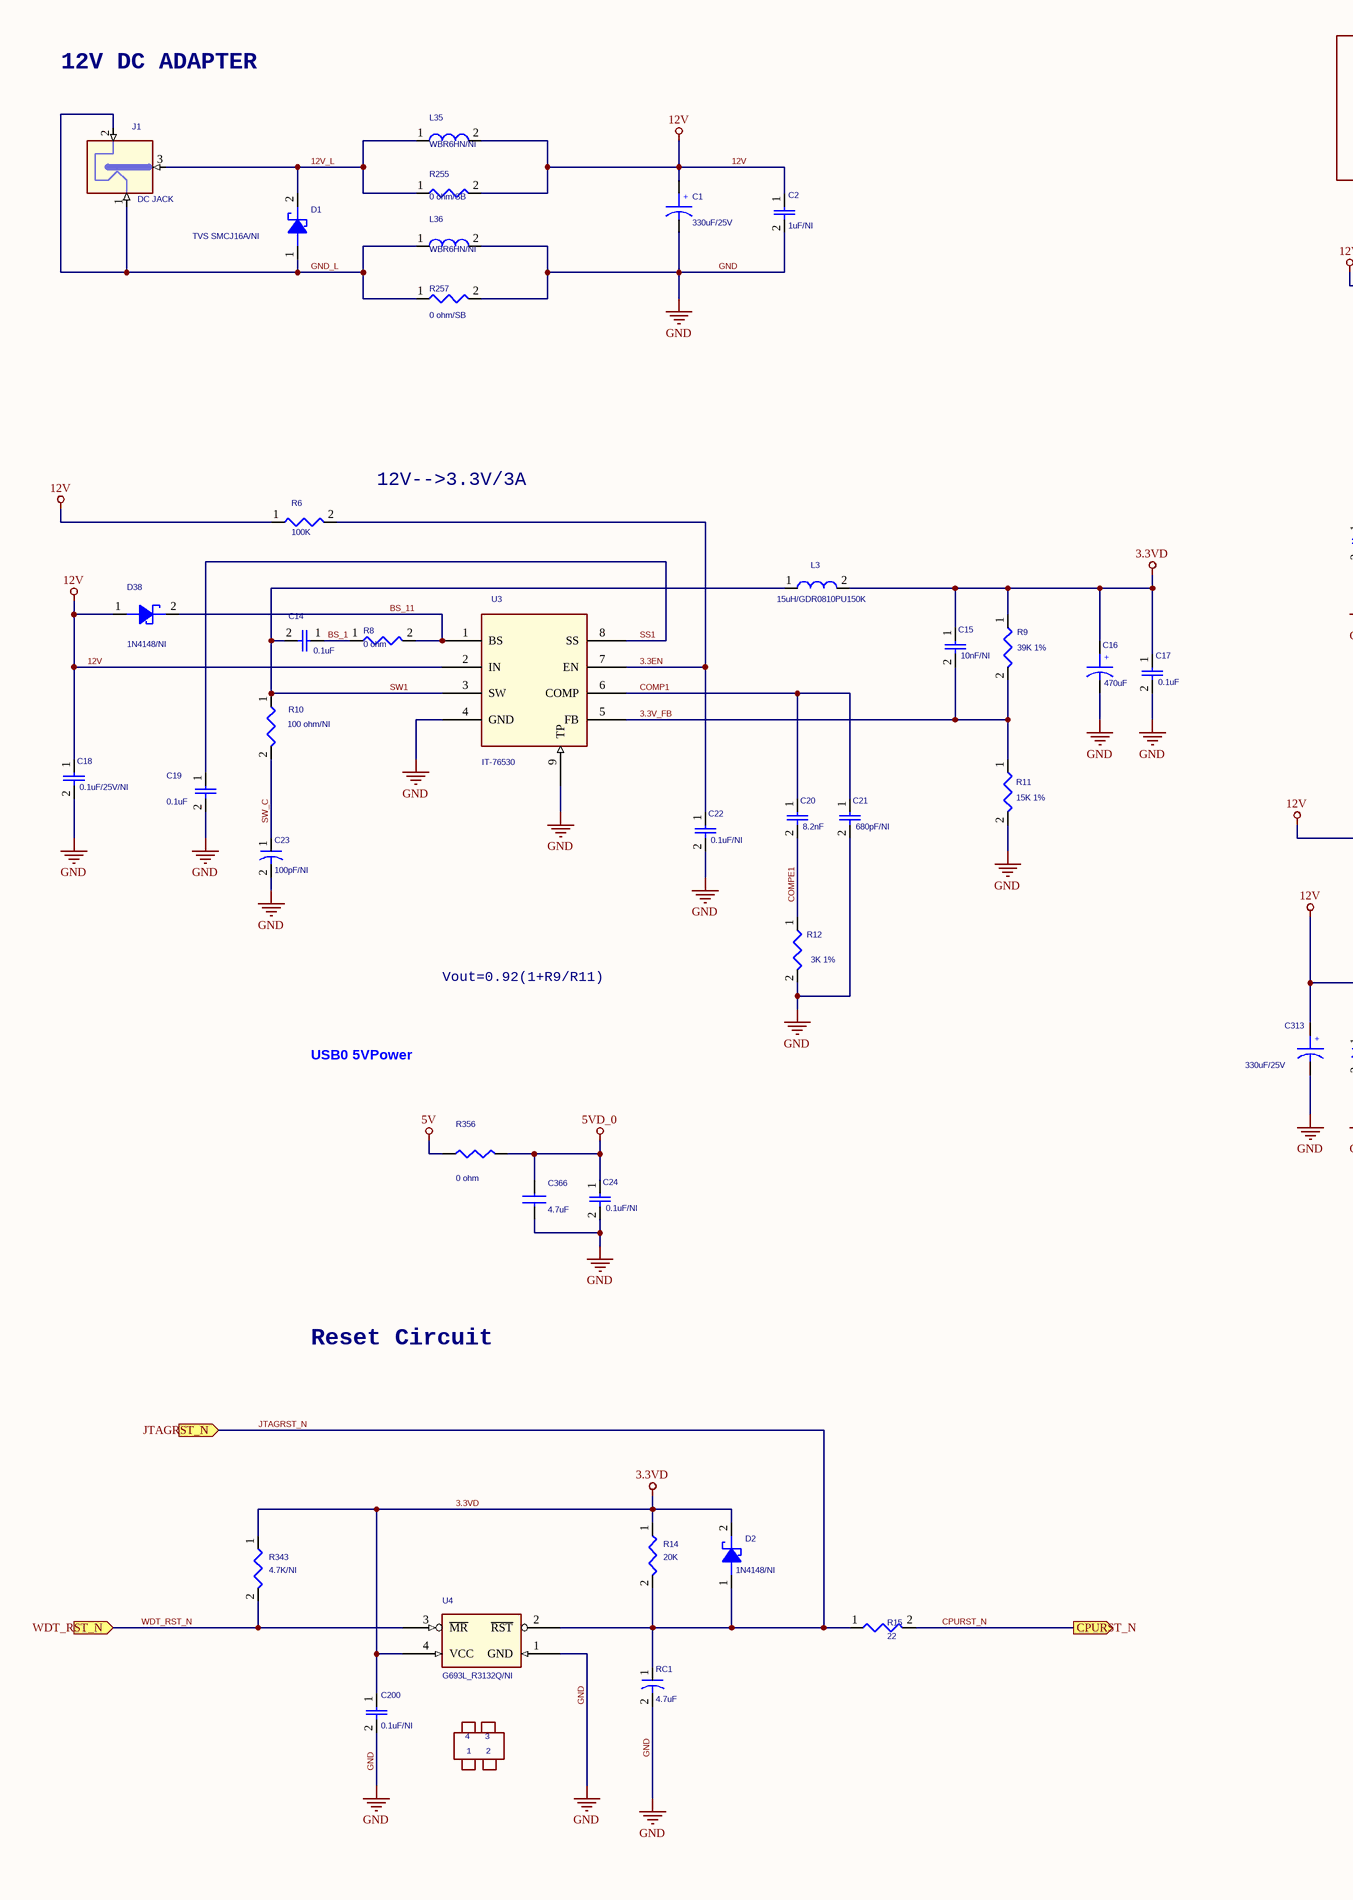
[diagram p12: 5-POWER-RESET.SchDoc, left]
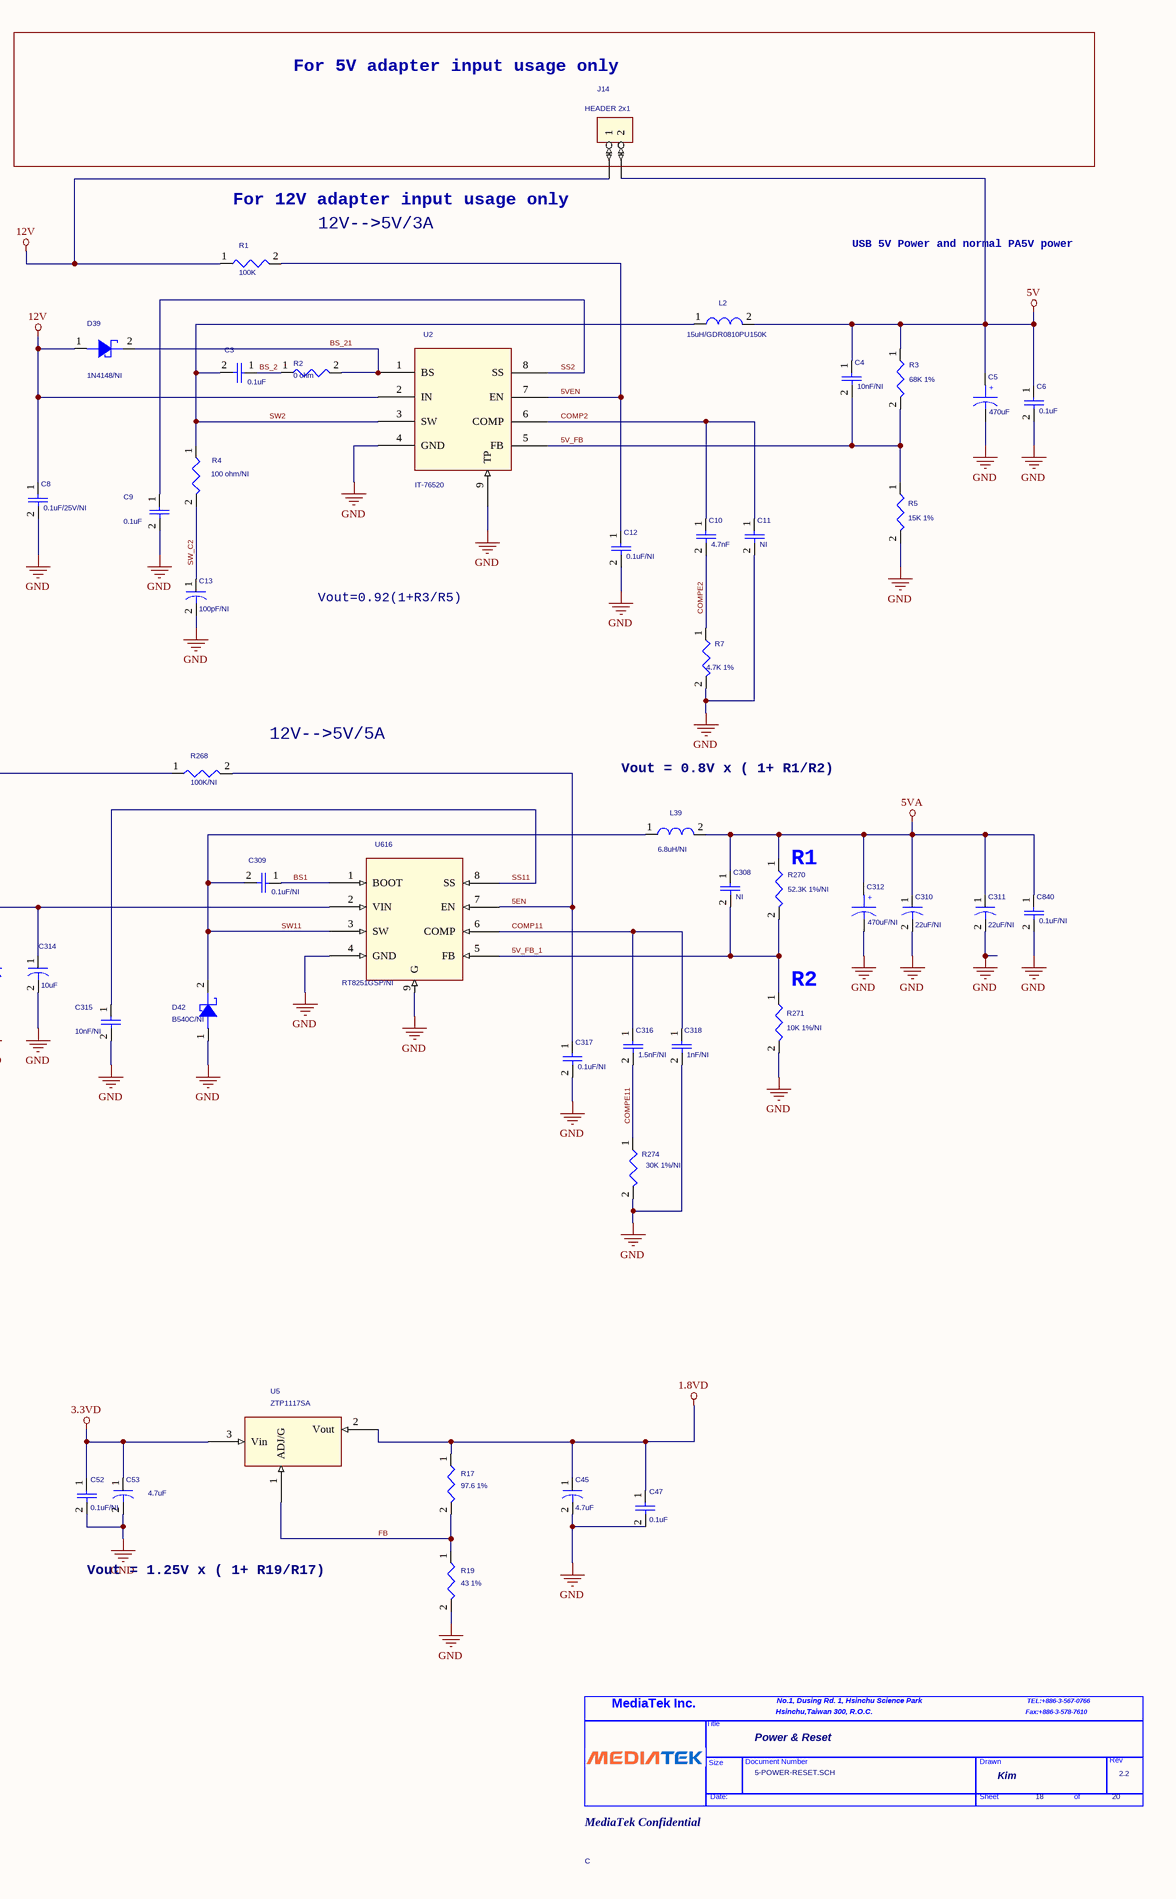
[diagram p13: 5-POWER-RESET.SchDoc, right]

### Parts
(Parts that share a designator on the sheet are numbered #1, #2 ... from top to bottom, then left to right.)
*#11  PIM: MediaTek Confidential  Page Count: 20  Page Number: 18  Page Size: C  Title: Power & Reset  RevCode: 2.2  Doc: 5-POWER-RESET.SCH  Designer: Kim  (hidden comment: TitleBlock_MTK4)  (graphical)
C1  330uF/25V  [C680UF6.3V/D8H11]
C2  1uF/NI  [C0402]
C3  0.1uF  [C0402]
C4  10nF/NI  [C0402]
C5  470uF  [C470UF16V/D8H11]
C6  0.1uF  [C0402]
C8  0.1uF/25V/NI  [C0603]
C9  0.1uF  [C0402]
C10  4.7nF  [C0402]
C11  NI  [C0402]
C12  0.1uF/NI  [C0402]
C13  100pF/NI  [C0603]
C14  0.1uF  [C0402]
C15  10nF/NI  [C0402]
C16  470uF  [C470UF16V/D8H11]
C17  0.1uF  [C0402]
C18  0.1uF/25V/NI  [C0603]
C19  0.1uF  [C0402]
C20  8.2nF  [C0402]
C21  680pF/NI  [C0402]
C22  0.1uF/NI  [C0402]
C23  100pF/NI  [C0603]
C24  0.1uF/NI  [C0402]
C45  4.7uF  [C0805]
C47  0.1uF  [C0402]
C52  0.1uF/NI  [C0402]
C53  4.7uF  [C0603]
C200  0.1uF/NI  [C0402]
C308  NI  [C0402]
C309  0.1uF/NI  [C0402]
C310  22uF/NI  [C1210]
C311  22uF/NI  [C1210]
C312  470uF/NI  [C330UF25V/D8H11]
C313  330uF/25V  [C330UF25V/D8H11]
C314  10uF  [C0805]
C315  10nF/NI  [C0402]
C316  1.5nF/NI  [C0402]
C317  0.1uF/NI  [C0402]
C318  1nF/NI  [C0402]
C366  4.7uF  [C0603]
C840  0.1uF/NI  [C0402]
D1  TVS SMCJ16A/NI  [VARISTOR/SMD/TVM5B150L103RY]
D2  1N4148/NI  [C0402]
D38  1N4148/NI  [C0402]
D39  1N4148/NI  [C0402]
D42  B540C/NI  [D/SMD/P6.61/B540C]
J1  DC JACK  [DC-JACK/3P/DIP/R/JD003-PF]
J14  HEADER 2x1  [DIP2/P2.54]
L2  15uH/GDR0810PU150K  [L/IND/DIP/MCD-0808-150MU-J]
L3  15uH/GDR0810PU150K  [L/IND/DIP/MCD-0808-150MU-J]
L35  WBR6HN/NI  [L/IND/DIP/D6H14]
L36  WBR6HN/NI  [L/IND/DIP/D6H14]
L39  6.8uH/NI  [L/IND/SMD/GSTD6030PW-6R8M]
R1  100K  [R0402]
R2  0 ohm  [R0402]
R3  68K 1%  [R0402]
R4  100 ohm/NI  [R0603]
R5  15K 1%  [R0402]
R6  100K  [R0402]
R7  4.7K 1%  [R0402]
R8  0 ohm  [R0402]
R9  39K 1%  [R0402]
R10  100 ohm/NI  [R0603]
R11  15K 1%  [R0402]
R12  3K 1%  [R0402]
R14  20K  [R0402]
R15  22  [R0402]
R17  97.6 1%  [R0402]
R19  43 1%  [R0402]
R255  0 ohm/SB  [SB/1206]
R257  0 ohm/SB  [SB/1206]
R268  100K/NI  [R0402]
R270  52.3K 1%/NI  [R0402]
R271  10K 1%/NI  [R0402]
R274  30K 1%/NI  [R0402]
R343  4.7K/NI  [R0402]
R356  0 ohm  [R0805]
RC1  4.7uF  [C0603]
U2  IT-76520  [SOP8/SMD/P1.27/IT7653]
U3  IT-76530  [SOP8/SMD/P1.27/IT7653]
U4  G693L_R3132Q/NI  [SOT-143/SMD/G693]
U5  ZTP1117SA  [SOT223-3/SMD/P2.3/AX1007]
U616  RT8251GSP/NI  [SOP8/SMD/P1.27/RT8251]

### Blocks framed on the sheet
For 5V adapter input usage only: J14

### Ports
CPURST_N (out), JTAGRST_N (in), WDT_RST_N (in)

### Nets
1.8VD: C45.1 C47.1 R17.1 U5.2(Vout)
3.3VD: C15.1 C16.1 C17.1 C52.1 C53.1 C200.1 D2.2(CATHODE) L3.2 R9.1 R14.1 R343.1 U4.4(VCC) U5.3(Vin)
5V: C4.1 C5.1 C6.1 J14.2 L2.2 R3.1 R356.1
5VA: C308.1 C310.1 C311.1 C312.1 C840.1 L39.2 R270.1
5VD_0: C24.1 C366.1 R356.2
12V: C1.1 C2.1 C8.1 C18.1 C313.1 C314.1 D38.1(ANODE) D39.1(ANODE) J14.1 L35.2 R1.1 R6.1 R255.2 R268.1 U2.2(IN) U3.2(IN) U616.2(VIN)
GND: C1.2 C2.2 C5.2 C6.2 C8.2 C9.2 C11.2 C12.2 C13.2 C16.2 C17.2 C18.2 C19.2 C21.2 C22.2 C23.2 C24.2 C45.2 C47.2 C52.2 C53.2 C200.2 C310.2 C311.2 C312.2 C313.2 C314.2 C315.2 C317.2 C318.2 C366.2 C840.2 D42.1(ANODE) L36.2 R5.2 R7.2 R11.2 R12.2 R19.2 R257.2 R271.2 R274.2 RC1.2 U2.4(GND) U2.9(TP) U3.4(GND) U3.9(TP) U4.1(GND) U616.4(GND) U616.9(G)
3.3EN: C22.1 R6.2 U3.7(EN)
3.3V_FB: C15.2 R9.2 R11.1 U3.5(FB)
5EN: C317.1 R268.2 U616.7(EN)
5V_FB: C4.2 R3.2 R5.1 U2.5(FB)
5V_FB_1: C308.2 R270.2 R271.1 U616.5(FB)
5VEN: C12.1 R1.2 U2.7(EN)
12V_L: D1.2(CATHODE) J1.3 L35.1 R255.1
BS1: C309.1 U616.1(BOOT)
BS_1: C14.1 R8.1
BS_2: C3.1 R2.1
BS_11: D38.2(CATHODE) R8.2 U3.1(BS)
BS_21: D39.2(CATHODE) R2.2 U2.1(BS)
COMP1: C20.1 C21.1 U3.6(COMP)
COMP2: C10.1 C11.1 U2.6(COMP)
COMP11: C316.1 C318.1 U616.6(COMP)
COMPE1: C20.2 R12.1
COMPE2: C10.2 R7.1
COMPE11: C316.2 R274.1
CPURST_N: R15.2 ; port CPURST_N
FB: R17.2 R19.1 U5.1(ADJ/G)
GND_L: D1.1(ANODE) J1.1 J1.2 L36.1 R257.1
JTAGRST_N: D2.1(ANODE) R14.2 R15.1 RC1.1 U4.2(~{RST}) ; port JTAGRST_N
SS1: C19.1 U3.8(SS)
SS2: C9.1 U2.8(SS)
SS11: C315.1 U616.8(SS)
SW1: C14.2 L3.1 R10.1 U3.3(SW)
SW2: C3.2 L2.1 R4.1 U2.3(SW)
SW11: C309.2 D42.2(CATHODE) L39.1 U616.3(SW)
SW_C: C23.1 R10.2
SW_C2: C13.1 R4.2
WDT_RST_N: R343.2 U4.3(~{MR}) ; port WDT_RST_N

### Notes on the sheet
- 12V DC ADAPTER
- For 12V adapter input usage only
- 12V-->5V/3A
- USB 5V Power and normal PA5V power
- 12V-->3.3V/3A
- Vout=0.92(1+R3/R5)
- 12V-->5V/5A
- Vout = 0.8V x ( 1+ R1/R2)
- (near R270) R1
- Vout=0.92(1+R9/R11)
- USB0 5VPower
- (near R271) R2
- Reset Circuit
- Vout = 1.25V x ( 1+ R19/R17)
- 4
- 1
- 3
- 2

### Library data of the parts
C1 C5 C16 C312 C313 = CAPACITOR POL
C2 = CAP/0402_Dup2
C3 C4 C6 C8-C12 C14 C15 C17-C22 C24 C308 C309 C315-C318 C840 = CAP/0402_Dup2: 1st Part Field: 0402
C13 C23 = CAP/0603_Dup1
C45 C53 C310 C311 C314 = CAP/1210_1206
C47 C52 = CAP/0402_0
C200 = CAP/0402_1
C366 = CAPACITOR NON-POL
D1 = DIODE SCHOTTKY
D2 D38 D39 = DIODE SK34A_Dup1
D42 = DIODE SK34A
L2 L3 L39 = L/GDR1012
L35 L36 = L/1206
R1 R3 R5-R7 R9 R11 R12 R255 R257 R268 R270 R271 R274 = RES/0402_1_Dup1
R2 R8 = RES/0402_Dup3
R4 R10 = RES/0603
R14 R15 R17 R19 R343 = RES/0402_3
R356 = R_Dup1
RC1 = CAP/0603_Dup2
U2 = CAT71990_0
U3 = CAT71990_1
U4 = IC DET SOT-143/SC-82AB
U5 = LDO RT9164A-SOT223_1
U616 = REG RT8251GSP

## Sheet 18-GPHY2-IP1001.SchDoc
size 513 x 386 mm
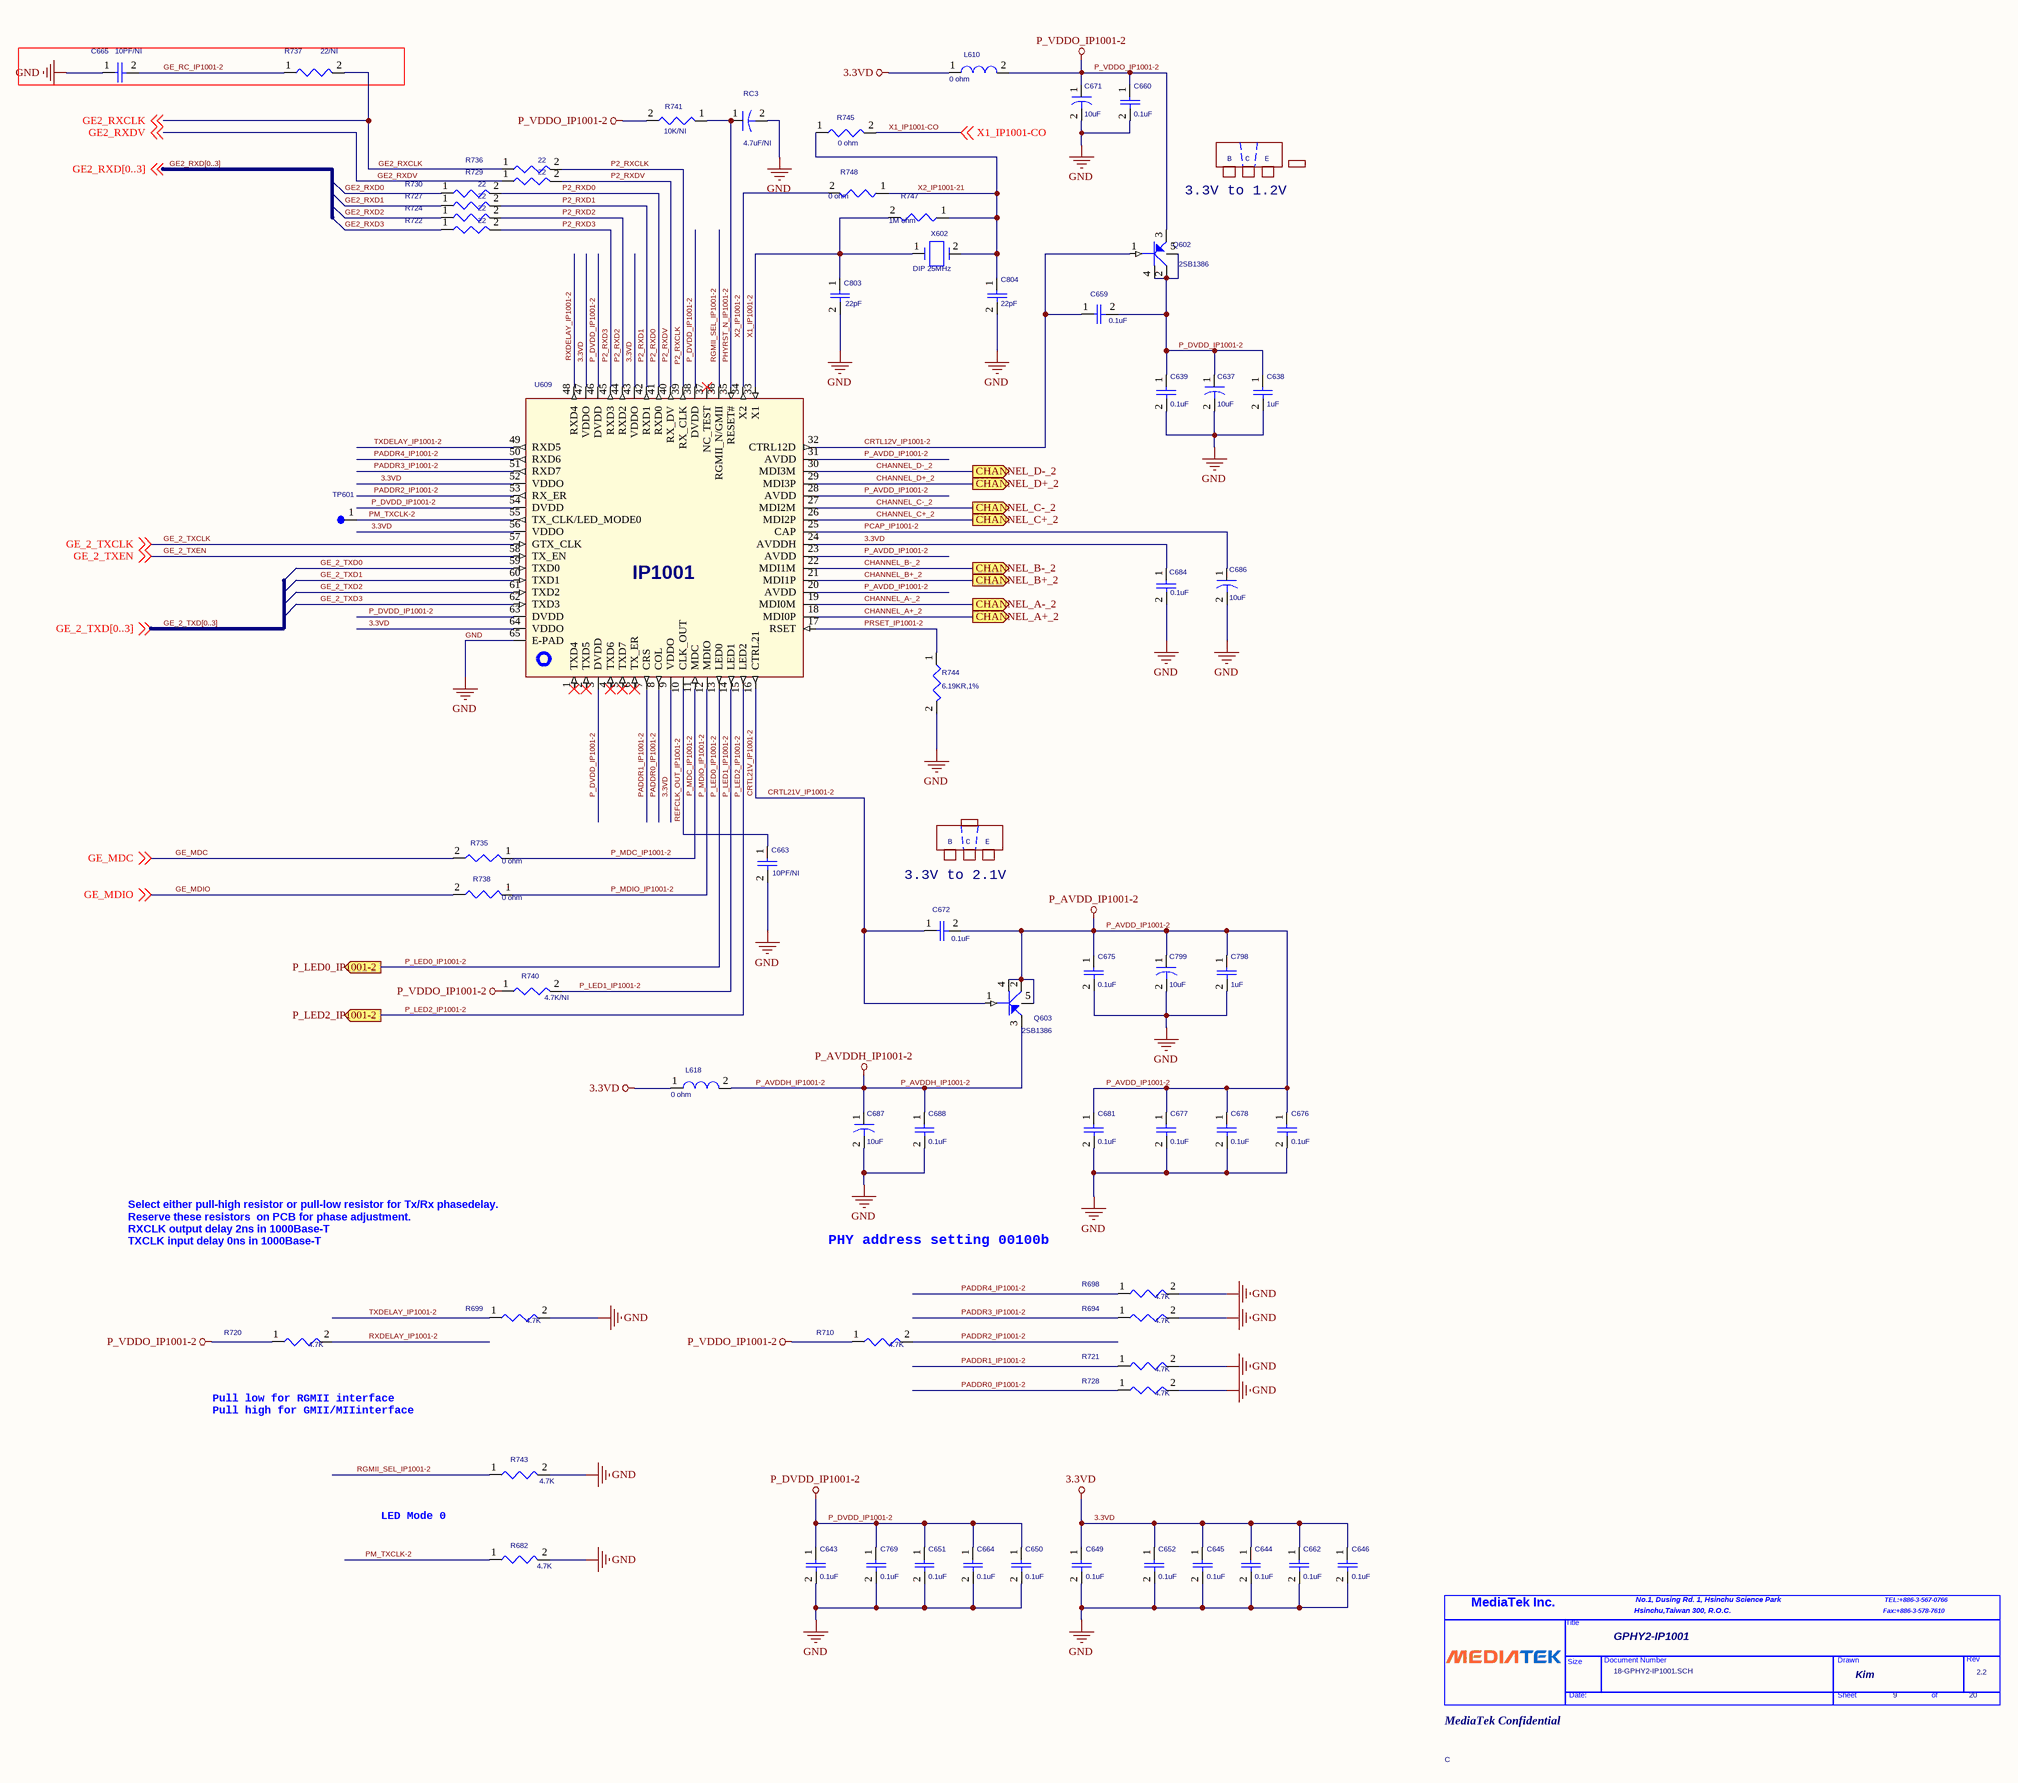
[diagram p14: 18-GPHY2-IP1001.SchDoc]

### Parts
(Parts that share a designator on the sheet are numbered #1, #2 ... from top to bottom, then left to right.)
*#12  PIM: MediaTek Confidential  Page Count: 20  Page Number: 9  Page Size: C  Title: GPHY2-IP1001  RevCode: 2.2  Doc: 18-GPHY2-IP1001.SCH  Designer: Kim  (hidden comment: TitleBlock_MTK4)  (graphical)
C637  10uF  [C0805]
C638  1uF  [C0402]
C639  0.1uF  [C0402]
C643  0.1uF  [C0402]
C644  0.1uF  [C0402]
C645  0.1uF  [C0402]
C646  0.1uF  [C0402]
C649  0.1uF  [C0402]
C650  0.1uF  [C0402]
C651  0.1uF  [C0402]
C652  0.1uF  [C0402]
C659  0.1uF  [C0402]
C660  0.1uF  [C0402]
C662  0.1uF  [C0402]
C663  10PF/NI  [C0402]
C664  0.1uF  [C0402]
C665  10PF/NI  [C0402]
C671  10uF  [C0805]
C672  0.1uF  [C0402]
C675  0.1uF  [C0402]
C676  0.1uF  [C0402]
C677  0.1uF  [C0402]
C678  0.1uF  [C0402]
C681  0.1uF  [C0402]
C684  0.1uF  [C0402]
C686  10uF  [C0805]
C687  10uF  [C0805]
C688  0.1uF  [C0402]
C769  0.1uF  [C0402]
C798  1uF  [C0402]
C799  10uF  [C0805]
C803  22pF  [C0402]
C804  22pF  [C0402]
L610  0 ohm  [L1206]
L618  0 ohm  [L1206]
Q602  2SB1386  [SOT-89/SMD/2SB1386]
Q603  2SB1386  [SOT-89/SMD/2SB1386]
R682  4.7K  [R0402]
R694  4.7K  [R0402]
R698  4.7K  [R0402]
R699  4.7K  [R0402]
R710  4.7K  [R0402]
R720  4.7K  [R0402]
R721  4.7K  [R0402]
R722  22  [R0402]
R724  22  [R0402]
R727  22  [R0402]
R728  4.7K  [R0402]
R729  22  [R0402]
R730  22  [R0402]
R735  0 ohm  [R0402]
R736  22  [R0402]
R737  22/NI  [R0402]
R738  0 ohm  [R0402]
R740  4.7K/NI  [R0402]
R741  10K/NI  [R0402]
R743  4.7K  [R0402]
R744  6.19KR,1%  [R0402]
R745  0 ohm  [R0402]
R747  1M ohm  [R0402]
R748  0 ohm  [R0402]
RC3  4.7uF/NI  [C0603]
TP601  SMD  [PAD/1P/0.5MM]  (value not drawn)
U609  IP1001  [QFN64/SMD/P0.5/IP1001]
X602  DIP 25MHz  [CRYS/DIP/D5X10.6/GB2000025/eCERA]

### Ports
CHANNEL_A+_2 (out), CHANNEL_A-_2 (out), CHANNEL_B+_2 (out), CHANNEL_B-_2 (out), CHANNEL_C+_2 (out), CHANNEL_C-_2 (out), CHANNEL_D+_2 (out), CHANNEL_D-_2 (out), P_LED0_IP1001-2 (out), P_LED2_IP1001-2 (out)

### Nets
3.3VD: C644.1 C645.1 C646.1 C649.1 C652.1 C662.1 C684.1 L610.1 L618.1 U609.9(VDDO) U609.24(AVDDH) U609.43(VDDO) U609.47(VDDO) U609.52(VDDO) U609.56(VDDO) U609.64(VDDO)
GND: C637.2 C638.2 C639.2 C643.2 C644.2 C645.2 C646.2 C649.2 C650.2 C651.2 C652.2 C660.2 C662.2 C663.2 C664.2 C665.1 C671.2 C675.2 C676.2 C677.2 C678.2 C681.2 C684.2 C686.2 C687.2 C688.2 C769.2 C798.2 C799.2 C803.2 C804.2 R682.2 R694.2 R698.2 R699.2 R721.2 R728.2 R743.2 R744.2 RC3.2 U609.65(E-PAD)
P_AVDD_IP1001-2: C672.2 C675.1 C676.1 C677.1 C678.1 C681.1 C798.1 C799.1 Q603.2(COLLECTOR) Q603.4(COLLECTOR) Q603.5(COLLECTOR) U609.20(AVDD) U609.23(AVDD) U609.28(AVDD) U609.31(AVDD)
P_AVDDH_IP1001-2: C687.1 C688.1 L618.2 Q603.3(EMITTER)
P_DVDD_IP1001-2: C637.1 C638.1 C639.1 C643.1 C650.1 C651.1 C659.2 C664.1 C769.1 Q602.2(COLLECTOR) Q602.4(COLLECTOR) Q602.5(COLLECTOR) U609.3(DVDD) U609.38(DVDD) U609.46(DVDD) U609.54(DVDD) U609.63(DVDD)
P_VDDO_IP1001-2: C660.1 C671.1 L610.2 Q602.3(EMITTER) R710.1 R720.1 R740.1 R741.2
CHANNEL_A+_2: U609.18(MDI0P) ; port CHANNEL_A+_2
CHANNEL_A-_2: U609.19(MDI0M) ; port CHANNEL_A-_2
CHANNEL_B+_2: U609.21(MDI1P) ; port CHANNEL_B+_2
CHANNEL_B-_2: U609.22(MDI1M) ; port CHANNEL_B-_2
CHANNEL_C+_2: U609.26(MDI2P) ; port CHANNEL_C+_2
CHANNEL_C-_2: U609.27(MDI2M) ; port CHANNEL_C-_2
CHANNEL_D+_2: U609.29(MDI3P) ; port CHANNEL_D+_2
CHANNEL_D-_2: U609.30(MDI3M) ; port CHANNEL_D-_2
CRTL12V_IP1001-2: C659.1 Q602.1(BASE) U609.32(CTRL12D)
CRTL21V_IP1001-2: C672.1 Q603.1(BASE) U609.16(CTRL21)
GE2_RXCLK: R736.1 R737.2 ; off-sheet GE2_RXCLK
GE2_RXD0: R730.1
GE2_RXD1: R727.1
GE2_RXD2: R724.1
GE2_RXD3: R722.1
GE2_RXDV: R729.1 ; off-sheet GE2_RXDV
GE_2_TXCLK: U609.57(GTX_CLK) ; off-sheet GE_2_TXCLK
GE_2_TXD0: U609.59(TXD0)
GE_2_TXD1: U609.60(TXD1)
GE_2_TXD2: U609.61(TXD2)
GE_2_TXD3: U609.62(TXD3)
GE_2_TXEN: U609.58(TX_EN) ; off-sheet GE_2_TXEN
GE_MDC: R735.2 ; off-sheet GE_MDC
GE_MDIO: R738.2 ; off-sheet GE_MDIO
GE_RC_IP1001-2: C665.2 R737.1
P2_RXCLK: R736.2 U609.39(RX_CLK)
P2_RXD0: R730.2 U609.41(RXD0)
P2_RXD1: R727.2 U609.42(RXD1)
P2_RXD2: R724.2 U609.44(RXD2)
P2_RXD3: R722.2 U609.45(RXD3)
P2_RXDV: R729.2 U609.40(RX_DV)
P_LED0_IP1001-2: U609.13(LED0) ; port P_LED0_IP1001-2
P_LED1_IP1001-2: R740.2 U609.14(LED1)
P_LED2_IP1001-2: U609.15(LED2) ; port P_LED2_IP1001-2
P_MDC_IP1001-2: R735.1 U609.11(MDC)
P_MDIO_IP1001-2: R738.1 U609.12(MDIO)
PADDR0_IP1001-2: R728.1 U609.8(COL)
PADDR1_IP1001-2: R721.1 U609.7(CRS)
PADDR2_IP1001-2: R710.2 U609.53(RX_ER)
PADDR3_IP1001-2: R694.1 U609.51(RXD7)
PADDR4_IP1001-2: R698.1 U609.50(RXD6)
PCAP_IP1001-2: C686.1 U609.25(CAP)
PHYRST_N_IP1001-2: R741.1 RC3.1 U609.35(RESET#)
PM_TXCLK-2: R682.1 TP601.1 U609.55(TX_CLK/LED_MODE0)
PRSET_IP1001-2: R744.1 U609.17(RSET)
REFCLK_OUT_IP1001-2: C663.1 U609.10(CLK_OUT)
RGMII_SEL_IP1001-2: R743.1 U609.36(RGMII_N/GMII)
RXDELAY_IP1001-2: R720.2 U609.48(RXD4)
TXDELAY_IP1001-2: R699.1 U609.49(RXD5)
X1_IP1001-2: C803.1 R747.2 U609.33(X1) X602.1
X1_IP1001-CO: R745.2 ; off-sheet X1_IP1001-CO
X2_IP1001-2: R748.2 U609.34(X2)
X2_IP1001-21: C804.1 R745.1 R747.1 R748.1 X602.2

Not connected (* = marked no-connect by the designer): U609 1(TXD4)* 2(TXD5)* 4(TXD6)* 5(TXD7)* 6(TX_ER)* 37(NC_TEST)*

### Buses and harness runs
bus GE2_RXD[0..3]
bus GE_2_TXD[0..3]

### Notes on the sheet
- B
- C
- E
- (near Q602) 3.3V to 1.2V
- (near C672) 3.3V to 2.1V
- PHY address setting 00100b
- (near R699) Select either pull-high resistor or pull-low resistor for Tx/Rx phasedelay.
  Reserve these resistors  on PCB for phase adjustment.
  RXCLK output delay 2ns in 1000Base-T
  TXCLK input delay 0ns in 1000Base-T
- Pull low for RGMII interface
  Pull high for GMII/MIIinterface
- LED Mode 0

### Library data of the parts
C637 C671 C686 C687 C799 = CAP/0805
C638 C639 C643-C646 C649-C652 C659 C660 C662-C664 C672 C675-C678 C681 C684 C688 C769 C798 C803 C804 = CAP/0402_Dup2
C665 = CAP/0402_Dup1
L610 L618 = L/0805_0603
Q602 = BJT 2SB1386-PNP_2
Q603 = BJT 2SB1386-PNP_3_Dup1
R682 R694 R698 R699 R710 R720-R722 R724 R727-R730 R735-R738 R740 R741 R743-R745 R747 R748 = RES/0402_Dup2
RC3 = CAP/0603_Dup2
TP601 = TP-SMD
U609 = IP1001_0
X602 = CRYSTAL-3x9_0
